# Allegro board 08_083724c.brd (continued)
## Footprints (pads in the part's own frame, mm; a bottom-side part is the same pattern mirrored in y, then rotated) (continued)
C1210H106
  rect 1.092x2.057 smd: 1(-1.646,0) 2(1.646,0)
C7343-31-2
  rect 3.353x2.438 smd: N(2.6,0) P(-2.6,0)
CNBERG1X6H205LD36
  rect 1.651x1.651 hole 1.143: 1(0,0)
  round 1.651 hole 1.143: 2(2.54,0) 3(5.08,0) 4(7.62,0) 5(10.16,0) 6(12.7,0)
CNKEY5016TP
  rect 4.699x3.429 smd: 1(0,0)
CNSAMTEC1X2H330LD36
  rect 1.651x1.651 hole 1.143: 1(-1.27,0)
  round 1.651 hole 1.143: 2(1.27,0)
CNTHMHDR2X5L500W200H215
  rect 1.143x1.143 hole 0.737: 1(0,0)
  round 1.143 hole 0.737: 2(0,1.27) 3(1.27,0) 4(1.27,1.27) 5(2.54,0) 6(2.54,1.27) 7(3.81,0) 8(3.81,1.27) 9(5.08,0) 10(5.08,1.27)
CNWURTH632723300011
  rect 0.305x1.194 smd: A1(-2.75,4.577) A2(-2.25,4.577) A3(-1.75,4.577) A4(-1.25,4.577) A5(-0.75,4.577) A6(-0.25,4.577) A7(0.25,4.577) A8(0.75,4.577) A9(1.25,4.577) A10(1.75,4.577) A11(2.25,4.577) A12(2.75,4.577)
  round 0.66 hole 0.406: B1(2.8,3.33) B2(2.4,2.63) B3(1.6,2.63) B4(1.2,3.33) B5(0.8,2.63) B6(0.4,3.33) B7(-0.4,3.33) B8(-0.8,2.63) B9(-1.2,3.33) B10(-1.6,2.63) B11(-2.4,2.63) B12(-2.8,3.33) GND1(-2,3.33) GND2(2,3.33)
  oval 0.991x1.6 hole 0.61x1.219: SH1(-4.27,2.18) SH2(4.27,2.18) SH3(4.27,-2.55) SH4(-4.27,-2.55)
  rect 0.203x0.991 smd: SH5(0,-0.005) SH6(0,-3.105)
CNWURTH693071010811
  rect 0.787x1.499 smd: 1(1.94,-3.099) 2(0.84,-2.699) 3(-0.26,-3.099) 4(-1.36,-3.299) 5(-2.46,-3.099) 6(-3.56,-3.299) 7(-4.66,-3.099) 8(-5.76,-3.099)
  rect 1.397x1.905 smd: 9_1(6.6,-6.952) 9_2(-6.55,-5.952)
  rect 1.803x1.397 smd: 10_1(0.752,7.201) 10_2(-4.948,7.201)
DFN2_1_6X1
  rect 0.508x0.787 smd: A(0.604,0) C(-0.604,0)
DFN8_3X2_PAD2_15X0_56_05-08-1702
  oval 0.305x0.838 smd: 1(-0.75,-0.95) 2(-0.25,-0.95) 3(0.25,-0.95) 4(0.75,-0.95) 5(0.75,0.95) 6(0.25,0.95) 7(-0.25,0.95) 8(-0.75,0.95)
  rect 2.159x0.61 smd: 9(0,0)
DO214ACH87
  rect 2.007x2.007 smd: A(2,0) C(-2,0)
FC2QFN15_F153A3FY_2
  rect 0.864x0.305 smd: 1(-1.618,0.95)
  rect 0.838x0.305 smd: 2(-1.631,0.45) 8(1.631,0.45) 9(1.631,0.95)
  rect 0.914x0.305 smd: 3(-1.593,-0.45) 7(1.593,-0.45)
  custom 0.241x0.241 smd: 4(-1.288,-1.438) 6(1.288,-1.438)
  custom 0.152x0.152 smd: 5(0,-0.473)
  custom 0.216x0.216 smd: 10(1.339,1.489) 15(-1.339,1.489)
  rect 0.305x0.838 smd: 11(0.75,1.756) 12(0.25,1.756) 13(-0.25,1.756) 14(-0.75,1.756)
FINGER274P_E4P
  rect 0.356x2.845 smd: 1(-32,0) 2(-31.75,0) 3(-31.5,0) 4(-31.25,0) 5(-31,0) 6(-30.75,0) 7(-30.5,0) 8(-30.25,0) 9(-30,0) 10(-29.75,0) 11(-29.5,0) 12(-29.25,0) 13(-29,0) 14(-28.75,0) 15(-28.5,0) 16(-28.25,0) 17(-28,0) 18(-27.75,0) 19(-27.5,0) 20(-27.25,0) 21(-27,0) 22(-26.75,0) 23(-26.5,0) 24(-26.25,0) 25(-26,0) 26(-25.75,0) 27(-25.5,0) 28(-25.25,0) 29(-25,0) 30(-24.75,0) 31(-24.5,0) 32(-24.25,0) 33(-24,0) 34(-23.75,0) 35(-23.5,0) 36(-23.25,0) 37(-23,0) 38(-22.75,0) 39(-22.5,0) 40(-22.25,0) 41(-22,0) 42(-21.75,0) 43(-21.5,0) 44(-21.25,0) 45(-21,0) 46(-20.75,0) 47(-20.5,0) 48(-20.25,0) 49(-20,0) 50(-19.75,0) 51(-19.5,0) 52(-19.25,0) 53(-19,0) 54(-18.75,0) 55(-18.5,0) 56(-18.25,0) 57(-18,0) 58(-17.75,0) 59(-17.5,0) 60(-17.25,0) 61(-17,0) 62(-16.75,0) 63(-16.5,0) 64(-16.25,0) 65(-16,0) 66(-15.75,0) 67(-15.5,0) 68(-15.25,0) 69(-15,0) 70(-14.75,0) 71(-14.5,0) 72(-14.25,0) 73(-14,0) 74(-13.75,0) 75(-13.5,0) 76(-13.25,0) 77(-13,0) 78(-12.75,0) 79(-12.5,0) 80(-12.25,0) 81(-12,0) 82(-11.75,0) 83(-11.5,0) 84(-11.25,0) 85(-11,0) 86(-10.75,0) 87(-10.5,0) 88(-10.25,0) 89(-10,0) 90(-9.75,0) 91(-9.5,0) 92(-9.25,0) 93(-9,0) 94(-8.75,0) 95(-8.5,0) 96(-8.25,0) 97(-8,0) 98(-7.75,0) 99(-7.5,0) 100(-7.25,0) 101(-7,0) 102(-6.75,0) 103(-6.5,0) 104(-6.25,0) 105(-6,0) 106(-5.75,0) 107(-5.5,0) 108(-5.25,0) 109(-5,0) 110(-4.75,0) 111(-4.5,0) 112(-4.25,0) 113(-4,0) 114(-3.75,0) 115(-3.5,0) 116(-3.25,0) 117(-3,0) 118(-2.75,0) 119(-2.5,0) 120(-2.25,0) 121(-2,0) 122(-1.75,0) 123(-1.5,0) 124(-1.25,0) 125(-1,0) 133(1,0) 134(1.25,0) 135(1.5,0) 136(1.75,0) 137(2,0) 138(2.25,0) 139(2.5,0) 140(2.75,0) 141(3,0) 142(3.25,0) 143(3.5,0) 144(3.75,0) 145(4,0) 146(4.25,0) 147(4.5,0) 148(4.75,0) 149(5,0) 150(5.25,0) 151(5.5,0) 152(5.75,0) 153(6,0) 154(6.25,0) 155(6.5,0) 156(6.75,0) 157(7,0) 158(7.25,0) 159(7.5,0) 160(7.75,0) 161(8,0) 162(8.25,0) 163(8.5,0) 164(8.75,0) 165(9,0) 166(9.25,0) 167(9.5,0) 168(9.75,0) 169(10,0) 170(10.25,0) 171(10.5,0) 172(10.75,0) 173(11,0) 174(11.25,0) 175(11.5,0) 176(11.75,0) 177(12,0) 178(12.25,0) 179(12.5,0) 180(12.75,0) 181(13,0) 182(13.25,0) 183(13.5,0) 184(13.75,0) 185(14,0) 186(14.25,0) 187(14.5,0) 188(14.75,0) 189(15,0) 190(15.25,0) 191(15.5,0) 192(15.75,0) 193(16,0) 194(16.25,0) 195(16.5,0) 196(16.75,0) 197(17,0) 198(17.25,0) 199(17.5,0) 200(17.75,0) 201(18,0) 202(18.25,0) 203(18.5,0) 204(18.75,0) 205(19,0) 206(19.25,0) 207(19.5,0) 208(19.75,0) 209(20,0) 210(20.25,0) 211(20.5,0) 212(20.75,0) 213(21,0) 214(21.25,0) 215(21.5,0) 216(21.75,0) 217(22,0) 218(22.25,0) 219(22.5,0) 220(22.75,0) 221(23,0) 222(23.25,0) 223(23.5,0) 224(23.75,0) 225(24,0) 226(24.25,0) 227(24.5,0) 228(24.75,0) 229(25,0) 230(25.25,0) 231(25.5,0) 232(25.75,0) 233(26,0) 234(26.25,0) 235(26.5,0) 236(26.75,0) 237(27,0) 238(27.25,0) 239(27.5,0) 240(27.75,0) 241(28,0) 242(28.25,0) 243(28.5,0) 244(28.75,0) 245(29,0) 246(29.25,0) 247(29.5,0) 248(29.75,0) 249(30,0) 250(30.25,0) 251(30.5,0) 252(30.75,0) 253(31,0) 254(31.25,0) 255(31.5,0) 256(31.75,0) 257(32,0) 258(32.25,0) 259(32.5,0) 260(32.75,0) 261(33,0) 262(33.25,0) 263(33.5,0) 264(33.75,0) 265(34,0) 266(34.25,0) 267(34.5,0) 268(34.75,0) 269(35,0) 270(35.25,0) 271(35.5,0) 272(35.75,0) 273(36,0) 274(36.25,0) 275(36.5,0) 276(36.75,0) 277(37,0) 278(37.25,0) 279(37.5,0) 280(37.75,0) 281(38,0)
  rect 4.826x2.845 smd: E1(-39.75,0) E2(-39.5,0) E3(-34.75,0) E4(-34.5,0)
L0805
  rect 1.194x1.448 smd: 1(-0.85,0) 2(0.85,0)
L1206
  rect 1.524x1.575 smd: 1(-1.714,0) 2(1.714,0)
LED0603
  rect 0.965x0.762 smd: A(0.8,0) C(-0.8,0)
LED0603-2
  rect 0.787x0.787 smd: A(0.787,0) C(-0.787,0)
LED0805_A
  rect 1.245x1.092 smd: A(1.172,0) C(-1.172,0)
LSML126W138H118
  rect 0.813x3.2 smd: 1(-0.902,0) 2(0.902,0)
LSMSQ157H122
  rect 0.965x3.708 smd: 1(-1.181,0) 2(1.181,0)
QFN16_2_6X1_8_A
  oval 0.203x0.787 smd: 1(-0.6,-0.9) 2(-0.2,-0.9) 3(0.2,-0.9) 4(0.6,-0.9) 9(0.6,0.9) 10(0.2,0.9) 11(-0.2,0.9) 12(-0.6,0.9)
  oval 0.787x0.203 smd: 5(1.3,-0.6) 6(1.3,-0.2) 7(1.3,0.2) 8(1.3,0.6) 13(-1.3,0.6) 14(-1.3,0.2) 15(-1.3,-0.2) 16(-1.3,-0.6)
QFN24_4X4_PAD2_1X2_1
  oval 0.305x0.991 smd: 1(-1.25,-2) 2(-0.75,-2) 3(-0.25,-2) 4(0.25,-2) 5(0.75,-2) 6(1.25,-2) 13(1.25,2) 14(0.75,2) 15(0.25,2) 16(-0.25,2) 17(-0.75,2) 18(-1.25,2)
  oval 0.991x0.305 smd: 7(2,-1.25) 8(2,-0.75) 9(2,-0.25) 10(2,0.25) 11(2,0.75) 12(2,1.25) 19(-2,1.25) 20(-2,0.75) 21(-2,0.25) 22(-2,-0.25) 23(-2,-0.75) 24(-2,-1.25)
  rect 2.108x2.108 smd: PAD(0,0)
QFN24_4X4_PAD2_5X2_5
  oval 0.305x0.991 smd: 1(-1.25,-2) 2(-0.75,-2) 3(-0.25,-2) 4(0.25,-2) 5(0.75,-2) 6(1.25,-2) 13(1.25,2) 14(0.75,2) 15(0.25,2) 16(-0.25,2) 17(-0.75,2) 18(-1.25,2)
  oval 0.991x0.305 smd: 7(2,-1.25) 8(2,-0.75) 9(2,-0.25) 10(2,0.25) 11(2,0.75) 12(2,1.25) 19(-2,1.25) 20(-2,0.75) 21(-2,0.25) 22(-2,-0.25) 23(-2,-0.75) 24(-2,-1.25)
  rect 2.489x2.489 smd: PAD(0,0)
QFN28_5X5_PAD3_5X3_5
  oval 0.305x0.838 smd: 1(-1.5,-2.45) 2(-1,-2.45) 3(-0.5,-2.45) 4(0,-2.45) 5(0.5,-2.45) 6(1,-2.45) 7(1.5,-2.45) 15(1.5,2.45) 16(1,2.45) 17(0.5,2.45) 18(0,2.45) 19(-0.5,2.45) 20(-1,2.45) 21(-1.5,2.45)
  oval 0.838x0.305 smd: 8(2.45,-1.5) 9(2.45,-1) 10(2.45,-0.5) 11(2.45,0) 12(2.45,0.5) 13(2.45,1) 14(2.45,1.5) 22(-2.45,1.5) 23(-2.45,1) 24(-2.45,0.5) 25(-2.45,0) 26(-2.45,-0.5) 27(-2.45,-1) 28(-2.45,-1.5)
  rect 3.505x3.505 smd: PAD(0,0)
QFN29_5X5_PAD1_66X1_7
  custom 0.087x0.087 smd: 1(-2.338,1.5) 2(-2.338,1) 3(-2.338,0.5) 4(-2.338,0) 5(-2.338,-0.5) 6(-2.338,-1) 7(-2.338,-1.5) 9(-1.437,-2.312) 10(-0.938,-2.312) 11(-0.437,-2.362) 12(0.437,-2.362) 13(0.938,-2.312) 14(1.437,-2.312) 16(2.338,-1.45) 17(2.338,-0.95) 18(2.338,-0.45) 19(2.338,0.45) 20(2.338,0.95) 21(2.338,1.45) 23(1.437,2.312) 24(0.938,2.312) 25(0.437,2.362) 26(-0.437,2.362) 27(-0.938,2.312) 28(-1.437,2.312)
  custom 0.249x0.249 smd: 8(-2.029,-2.075) 15(2.029,-2.075) 22(2.029,2.075) 29(-2.029,2.075)
  rect 1.75x1.71 smd: 30(0,0)
R0201
  rect 0.305x0.406 smd: 1(-0.318,0) 2(0.318,0)
R0402
  rect 0.635x0.737 smd: 1(-0.5,0) 2(0.5,0)
R0603
  rect 0.787x0.991 smd: 1(-0.85,0) 2(0.85,0)
R0805
  rect 1.041x1.397 smd: 1(-0.95,0) 2(0.95,0)
R1206-4P
  rect 1.753x1.092 smd: 1(-1.376,-0.696) 2(1.376,-0.696) 3(1.376,0.696) 4(-1.376,0.696)
R2512H35
  rect 2.108x3.988 smd: 1(-3.104,0) 2(3.104,0)
SC70-5_A
  rect 0.406x0.94 smd: 1(-0.65,-1.1) 2(0,-1.1) 3(0.65,-1.1) 4(0.65,1.1) 5(-0.65,1.1)
SO8
  rect 0.61x2.184 smd: 1(-1.905,-2.54) 2(-0.635,-2.54) 3(0.635,-2.54) 4(1.905,-2.54) 5(1.905,2.54) 6(0.635,2.54) 7(-0.635,2.54) 8(-1.905,2.54)
SOT23-5L
  rect 0.508x1.524 smd: 1(-0.95,-1.17) 2(0,-1.17) 3(0.95,-1.17) 4(0.95,1.17) 5(-0.95,1.17)
SOT23-5L-2
  rect 0.61x1.194 smd: 1(-0.95,-1.15) 2(0,-1.15) 3(0.95,-1.15) 4(0.95,1.15) 5(-0.95,1.15)
SOT23_6-3
  rect 0.635x1.067 smd: 1(-0.95,-1.1) 2(0,-1.1) 3(0.95,-1.1) 4(0.95,1.1) 5(0,1.1) 6(-0.95,1.1)
SOT353
  rect 0.33x0.94 smd: 1(-0.65,-0.89) 2(0,-0.89) 3(0.65,-0.89) 4(0.65,0.89) 5(-0.65,0.89)
SWSML137W244H177
  rect 1.092x1.499 smd: 1A(0,-4.449) 1B(0,4.449)
SWSML248W244H185
  rect 1.397x2.108 smd: 1(-1.998,-4.454) 2(-1.998,4.454) 3(1.998,-4.454) 4(1.998,4.454)
SWSMSQ394H268
  rect 1.194x2.591 smd: 1(-2.54,-5.995) 2(2.54,5.995) 4(2.54,-5.995) 8(-2.54,5.995) C1(0,-5.995) C2(0,5.995)
TBGA24
  round 0.33 smd: A2(-2,-1) A3(-2,0) A4(-2,1) A5(-2,2) B1(-1,-2) B2(-1,-1) B3(-1,0) B4(-1,1) B5(-1,2) C1(0,-2) C2(0,-1) C3(0,0) C4(0,1) C5(0,2) D1(1,-2) D2(1,-1) D3(1,0) D4(1,1) D5(1,2) E1(2,-2) E2(2,-1) E3(2,0) E4(2,1) E5(2,2)
TPSMC30
  round 0.762 smd: 1(0,0)
TSSOP14
  rect 1.651x0.33 smd: 1(-2.87,1.956) 2(-2.87,1.306) 3(-2.87,0.655) 4(-2.87,0.005) 5(-2.87,-0.645) 6(-2.87,-1.295) 7(-2.87,-1.946) 8(2.87,-1.946) 9(2.87,-1.295) 10(2.87,-0.645) 11(2.87,0.005) 12(2.87,0.655) 13(2.87,1.306) 14(2.87,1.956)
unnamed#2
  round 5.994 hole 3.2 unplated: (0,0)
VQFN12_2X2_5
  oval 1.041x0.406 smd: 1(-0.675,0.35) 2(-0.675,-0.35) 7(0.675,-0.35) 8(0.675,0.35)
  oval 0.203x0.61 smd: 3(-0.75,-1.15) 4(-0.25,-1.15) 5(0.25,-1.15) 6(0.75,-1.15) 9(0.75,1.15) 10(0.25,1.15) 11(-0.25,1.15) 12(-0.75,1.15)
WLCSP20-2
  round 0.203 smd: A1(-0.8,-0.6) A2(-0.8,-0.2) A3(-0.8,0.2) A4(-0.8,0.6) B1(-0.4,-0.6) B2(-0.4,-0.2) B3(-0.4,0.2) B4(-0.4,0.6) C1(0,-0.6) C2(0,-0.2) C3(0,0.2) C4(0,0.6) D1(0.4,-0.6) D2(0.4,-0.2) D3(0.4,0.2) D4(0.4,0.6) E1(0.8,-0.6) E2(0.8,-0.2) E3(0.8,0.2) E4(0.8,0.6)
XSM4PL126W98H39
  rect 1.194x0.991 smd: 1(-1.27,-0.989) 2(1.27,-0.989) 3(1.27,0.989) 4(-1.27,0.989)
YSML79W63H32
  rect 0.762x0.66 smd: 1(-0.66,-0.508) 2(0.66,-0.508) 3(0.66,0.508) 4(-0.66,0.508)
YSML126W98H31
  rect 1.397x1.194 smd: 1(-1.1,-0.95) 2(1.1,-0.95) 3(1.1,0.95) 4(-1.1,0.95)

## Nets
1V8_LDO0: C140.1 TP30.1(N1) U16.29
1V8_LDO2: C123.1 C124.1 TP29.1(N1) U16.6
1V8_LDO3: C138.1 C234.1 TP31.1(N1) U16.8
3V3: C61.2(N2) C63.1 C65.2(N2) C67.2(N2) C119.2(N2) C121.2(N2) C139.1 C141.1 C142.1 C143.1 C248.1 C249.1 C251.1 C252.1 L1.2(N2) P6.4 R104.1 R104.3 R116.1 R120.1 R124.2(N2) R221.1 U2.11 U9.A3(VSD) U10.E6 U10.F5 U10.J10 U10.K9 U16.11 U16.12 U16.18 U16.19 U22.3 U22.4
DGND: C1.1 C2.1 C3.1 C4.1 C5.2(N2) C6.1 C7.1 C8.1 C9.1 C10.1 C11.1 C12.1 C13.1 C14.2(N2) C15.1 C16.1 C17.1 C18.1 C19.1 C20.1 C21.1 C22.1 C23.1 C24.2(N2) C25.2(N2) C26.2(N2) C27.2(N2) C28.2(N2) C29.2(N2) C30.2(N2) C31.2(N2) C32.1 C33.1 C34.2(N2) C35.2(N2) C36.2(N2) C37.1 C38.2(N2) C39.2(N2) C40.2(N2) C41.2(N2) C42.2(N2) C43.2(N2) C44.2(N2) C45.2(N2) C46.2(N2) C47.2(N2) C48.2(N2) C49.2(N2) C50.1 C51.1 C52.1 C53.2(N2) C54.1 C55.2(N2) C56.1 C57.1 C58.1 C59.2(N2) C60.2(N2) C61.1 C62.1 C63.2(N2) C64.1 C65.1 C66.2(N2) C67.1 C68.1 C69.1 C70.1 C71.1 C72.2(N2) C86.2(N2) C87.2(N2) C88.2(N2) C89.2(N2) C90.2(N2) C91.2(N2) C92.2(N2) C93.2(N2) C94.2(N2) C95.2(N2) C96.2(N2) C97.2(N2) C98.1 C99.2(N2) C100.1 C101.1 C102.1 C103.1 C104.1 C105.2(N2) C106.2(N2) C107.2(N2) C108.1 C109.2(N2) C110.2(N2) C111.2(N2) C112.1 C113.2(N2) C114.1 C115.2(N2) C116.2(N2) C117.1 C118.1 C119.1 C120.2(N2) C121.1 C122.2(N2) C123.2(N2) C124.2(N2) C125.2(N2) C126.2(N2) C127.2(N2) C128.2(N2) C129.2(N2) C130.2(N2) C131.2(N2) C132.2(N2) C133.2(N2) C134.2(N2) C135.2(N2) C136.2(N2) C137.2(N2) C138.2(N2) C139.2(N2) C140.2(N2) C141.2(N2) C142.2(N2) C143.2(N2) C144.2(N2) C145.1 C146.2(N2) C147.1 C148.1 C149.1 C150.1 C151.1 C152.1 C153.1 C154.1 C155.1 C156.1 C157.1 C158.1 C159.1 C160.1 C161.1 C162.1 C163.2(N2) C164.2(N2) C165.2(N2) C166.2(N2) C167.2(N2) C168.2(N2) C169.2(N2) C170.2(N2) C171.2(N2) C172.2(N2) C173.2(N2) C174.2(N2) C175.2(N2) C176.2(N2) C177.2(N2) C178.2(N2) C179.2(N2) C180.2(N2) C181.2(N2) C182.2(N2) C183.2(N2) C184.2(N2) C185.2(N2) C186.2(N2) C187.2(N2) C188.2(N2) C189.2(N2) C190.2(N2) C191.2(N2) C192.2(N2) C193.2(N2) C194.2(N2) C195.2(N2) C196.2(N2) C197.2(N2) C198.2(N2) C199.2(N2) C200.2(N2) C201.2(N2) C202.2(N2) C203.2(N2) C204.2(N2) C205.2(N2) C206.2(N2) C207.2(N2) C208.2(N2) C209.2(N2) C210.2(N2) C211.2(N2) C212.2(N2) C213.2(N2) C214.2(N2) C215.2(N2) C216.2(N2) C217.2(N2) C218.2(N2) C219.2(N2) C220.2(N2) C221.2(N2) C222.2(N2) C223.2(N2) C224.2(N2) C225.2(N2) C226.2(N2) C227.2(N2) C228.2(N2) C229.2(N2) C230.2(N2) C231.2(N2) C232.2(N2) C233.2(N2) C234.2(N2) C235.2(N2) C236.2(N2) C238.2(N2) C239.2(N2) C240.2(N2) C241.1 C242.2(N2) C243.2(N2) C244.2(N2) C245.2(N2) C246.N(N2) C247.2(N2) C248.2(N2) C249.2(N2) C250.2(N2) C251.2(N2) C252.2(N2) C253.2(N2) C254.2(N2) C255.2(N2) C256.2(N2) C257.2(N2) C258.2(N2) C262.2(N2) D1.2 D1.5 D2.2 D3.A(P) D6.2 D8.A(P) P2.A1 P2.A12 P2.B1 P2.B12 P2.GND1 P2.GND2 P3.A1 P3.A12 P3.B1 P3.B12 P3.GND1 P3.GND2 P4.3 P4.5 P5.3 P5.5 P6.6 P6.9_1(N9) P6.9_2 P8.27 P8.28 P8.49 P8.50 P8.71 P8.72 P8.73 P8.85 P8.90 P8.97 P8.109 P8.110 P8.121 P8.124 P8.133 P8.134 P8.145 P8.148 P8.154 P8.157 P8.160 P8.166 P8.169 P8.174 P8.180 P8.181 P8.186 P8.191 P8.193 P8.196 P8.203 P8.206 P8.213 P8.216 P8.223 P8.229 P8.235 P8.238 P8.251 P8.260 P8.265 P8.268 P8.272 P8.278 P8.279 P8.280 P8.281 P8.E3 P8.E4 P12.5 P12.6(N6) R1.2(N2) R2.2(N2) R3.2(N2) R6.2(N2) R11.2(N2) R12.2(N2) R13.2(N2) R15.2(N2) R19.2(N2) R21.2(N2) R40.2(N2) R42.2(N2) R45.2(N2) R50.2(N2) R51.2(N2) R67.2(N2) R68.2(N2) R82.2(N2) R84.2(N2) R86.2(N2) R91.2(N2) R93.2(N2) R94.2(N2) R103.2(N2) R119.2(N2) R130.2(N2) R147.2(N2) R153.2(N2) R156.2(N2) R166.1 R167.1 R168.1 R169.1 R170.1 R206.2(N2) R208.2(N2) R209.2(N2) R211.2(N2) R212.2(N2) S4.1 S4.2 TP28.1(N1) U1.A1 U1.A11 U1.A22 U1.AA2 U1.AA5 U1.AA14 U1.AA15 U1.AA16 U1.AA17 U1.AA21(GND_99) U1.AB1 U1.AB4 U1.AB5 U1.AB14 U1.AB15 U1.AB16 U1.AB17 U1.AB22 U1.B2 U1.B6 U1.B17 U1.B21 U1.C1 U1.C3 U1.C5 U1.C7 U1.C16 U1.C18 U1.C20 U1.D4 U1.D6 U1.D8 U1.D12 U1.D15 U1.D17 U1.D19 U1.D22 U1.E5 U1.E18 U1.F6 U1.F11 U1.F13 U1.F17 U1.G16 U1.H8 U1.H9 U1.H10 U1.H11 U1.H12 U1.H13 U1.H14 U1.H15 U1.H17 U1.J1 U1.J7 U1.J10 U1.J13 U1.J16 U1.L1 U1.L7 U1.L9 U1.L10 U1.L11 U1.L12 U1.L13 U1.L14 U1.L16 U1.N1 U1.N7 U1.N9 U1.N10 U1.N11 U1.N12 U1.N13 U1.N14 U1.N16 U1.N22 U1.P22 U1.R7 U1.R16 U1.T7 U1.T9 U1.T11 U1.T13 U1.T15 U1.T16 U1.U6 U1.U17 U1.V5 U1.V8 U1.V15 U1.V16 U1.V17 U1.V18 U1.W4 U1.W6 U1.W14 U1.W15 U1.W16 U1.W17 U1.W18 U1.W19 U1.Y3 U1.Y5 U1.Y6 U1.Y14 U1.Y15 U1.Y16 U1.Y17 U1.Y20 U2.4 U2.6 U2.8 U3.A3 U3.A10 U3.AB3 U3.AB5 U3.AB8 U3.AB10 U3.C1 U3.C5 U3.C8 U3.C12 U3.D2 U3.D4 U3.D9 U3.D11 U3.E1 U3.E5 U3.E8 U3.E12 U3.G1 U3.G3 U3.G5 U3.G8 U3.G10 U3.G12 U3.J1 U3.J3 U3.J10 U3.J12 U3.K2 U3.K4 U3.K9 U3.K11 U3.N2 U3.N4 U3.N9 U3.N11 U3.P1 U3.P3 U3.P10 U3.P12 U3.T1 U3.T3 U3.T5 U3.T8 U3.T10 U3.T12 U3.V1 U3.V5 U3.V8 U3.V12 U3.W2 U3.W4 U3.W9 U3.W11 U3.Y1 U3.Y5 U3.Y8 U3.Y12 U4.19 U4.PAD U5.B3 U5.C1 U5.E5(VSSQ_2) U6.B3 U7.6 U7.7 U7.8 U7.9 U7.10 U7.11 U7.12 U8.6 U9.C2 U9.C3 U10.A6 U10.C4 U10.E7 U10.G5 U10.H10 U10.J5 U10.K8 U10.N2 U10.N5 U10.P4 U10.P6 U13.7 U14.3 U14.PAD U15.2 U15.5(WP) U16.4 U16.26 U16.30 U17.2 U17.5(WP) U18.3 U19.3 U20.9(ST) U20.12 U21.1 U21.9 U22.PAD U23.3 U29.7 Y1.2 Y1.4 Y2.2 Y4.2
VDD_EXT: C1.2(N2) C2.2(N2) C3.2(N2) C4.2(N2) C5.1 C6.2(N2) C7.2(N2) C8.2(N2) C9.2(N2) C32.2(N2) C53.1 C54.2(N2) C55.1 C56.2(N2) C57.2(N2) C58.2(N2) C59.1 C60.1 C62.2(N2) C68.2(N2) C69.2(N2) C70.2(N2) C71.2(N2) C72.1 C87.1 C90.1 C96.1 C125.1 C131.1 C132.1 C133.1 C134.1 C137.1 C163.1 C164.1 C165.1 C166.1 C167.1 C168.1 C169.1 C170.1 C171.1 C226.1 C228.1 C230.1 C232.1 C236.1 C241.2(N2) C242.1 C253.1 C254.1 C255.1 C256.1 C262.1 DS1.A(P) DS2.A(P) DS3.A(P) DS4.A(P) DS5.A(P) DS6.A(P) DS9.A(P) DS11.A(P) E2.2(N2) E3.2(N2) E4.2(N2) JP2.1 P10.2(N2) R4.1 R8.1 R9.1 R10.1 R14.1 R17.1 R18.1 R20.1 R38.1 R39.1 R44.1 R46.1 R47.1 R48.1 R66.1 R81.1 R83.1 R95.1 R96.1 R101.1 R109.2(N2) R112.2(N2) R113.1 R115.1 R117.1 R123.1 R127.1 R129.1 R132.1 R133.1 R134.1 R135.1 R136.1 R137.1 R138.1 R139.1 R140.1 R141.1 R145.1 R154.1 R155.1 R159.1 R207.2(N2) S2.C1 S2.C2 TP23.1(N1) U1.G7 U1.H7 U1.H16 U1.K7 U1.K16 U1.M7 U1.M16 U1.P7 U1.P16 U1.T10 U1.T12 U1.T14 U1.T22 U3.F1 U3.F12 U3.G4 U3.G9 U3.T4 U3.T9 U3.U1 U3.U12 U4.21(VCC) U5.B4 U5.D1 U5.E4 U6.B4 U7.14(VDD) U8.14(VDD) U9.A2 U10.C6 U10.M4 U10.N4 U10.P3 U10.P5 U13.1 U13.8 U15.4 U17.4 U18.5 U19.5 U21.4(VM) U21.5 U22.17(VDDIO) U22.21 U29.14(VCC) Y2.4(VDD) Y4.1 Y4.4(VDD)
VDD_INPUT: C97.1 C107.1 C128.1 C129.1 C135.1 C136.1 C239.1 C240.1 C243.1 C247.1 D7.C TP22.1(N1) U2.1 U2.3 U2.7 U20.1 U20.8 U23.7
VDD_INT: C34.1 C144.1 C172.1 C173.1 C174.1 C175.1 C176.1 C177.1 C178.1 C179.1 C180.1 C181.1 C182.1 C183.1 C184.1 C185.1 C186.1 C187.1 C188.1 C189.1 C190.1 C191.1 C192.1 C193.1 C194.1 C195.1 C196.1 C197.1 C198.1 C199.1 C200.1 C201.1 C202.1 C203.1 C204.1 C205.1 C206.1 C207.1 C208.1 C209.1 C210.1 C211.1 C212.1 C213.1 C214.1 C215.1 C216.1 C217.1 C218.1 C219.1 C220.1 C221.1 C222.1 C223.1 C224.1 P7.2(N2) R125.2(N2) R126.2(N2) R131.2(N2) TP20.1(N1) U1.J8 U1.J9 U1.J11 U1.J12 U1.J14 U1.J15 U1.K8 U1.K9 U1.K12 U1.K13 U1.K14 U1.K15 U1.L8 U1.L15 U1.M8 U1.M9 U1.M12 U1.M13 U1.M14 U1.M15 U1.N8 U1.N15 U1.P8 U1.P9 U1.P10 U1.P11 U1.P12 U1.P13 U1.P14 U1.P15 U1.R8 U1.R9 U1.R10 U1.R11 U1.R12 U1.R13 U1.R14 U1.R15 U1.T8
VDD_LPDD4_IO: C10.2(N2) C11.2(N2) C12.2(N2) C13.2(N2) C14.1 C15.2(N2) C16.2(N2) C17.2(N2) C18.2(N2) C19.2(N2) C20.2(N2) C21.2(N2) C22.2(N2) C23.2(N2) C35.1 C36.1 C38.1 C39.1 C40.1 C41.1 C42.1 C43.1 C44.1 C45.1 C46.1 C47.1 C48.1 C49.1 C50.2(N2) C51.2(N2) C52.2(N2) C98.2(N2) C99.1 C100.2(N2) C101.2(N2) C102.2(N2) C103.2(N2) C104.2(N2) C105.1 C106.1 C108.2(N2) C109.1 C110.1 C111.1 C112.2(N2) C113.1 C114.2(N2) C115.1 C116.1 C117.2(N2) C118.2(N2) C120.1 C122.1 C130.1 C145.2(N2) C146.1 C147.2(N2) C148.2(N2) C149.2(N2) C150.2(N2) C151.2(N2) C152.2(N2) C153.2(N2) C154.2(N2) C155.2(N2) C156.2(N2) C157.2(N2) C158.2(N2) C159.2(N2) C160.2(N2) C161.2(N2) C162.2(N2) C225.1 C227.1 C229.1 C231.1 C233.1 P9.2(N2) R16.1 R106.2(N2) R128.2(N2) R148.2(N2) R149.2(N2) R150.1 TP21.1(N1) U1.D9 U1.D10 U1.D11 U1.D13 U1.D14 U1.E8 U1.E9 U1.E10 U1.E11 U1.E12 U1.E13 U1.E14 U1.E15 U1.F8 U1.F9 U1.F10 U1.F14 U1.F15 U1.G8 U1.G9 U1.G10 U1.G11 U1.G12 U1.G13 U1.G14 U1.G15 U3.A4 U3.A9 U3.AA3 U3.AA5 U3.AA8 U3.AA10 U3.AB4 U3.AB9 U3.B3 U3.B5 U3.B8 U3.B10 U3.D1 U3.D5 U3.D8 U3.D12 U3.F3 U3.F5 U3.F8 U3.F10 U3.H1 U3.H5 U3.H8 U3.H12 U3.K1 U3.K3 U3.K10 U3.K12 U3.N1 U3.N3 U3.N10 U3.N12 U3.R1 U3.R5 U3.R8 U3.R12 U3.U3 U3.U5 U3.U8 U3.U10 U3.W1 U3.W5 U3.W8 U3.W12
VDD_SOM: P8.E1 P8.E2 R164.1
_N14: C26.1 C27.1 E3.1 U1.K10 U1.K11 U1.M10 U1.M11
_N15: C25.1 R143.2(N2) R158.1 Y1.1
_N16: C24.1 R142.1 R158.2(N2) Y1.3(IN/OUT2)
_N31: C28.1 C29.1 E4.1 U1.R22
_N36: C30.1 C31.1 C245.1 E2.1 U1.F12
_N50: JP2.2(S2) P5.1
_N51: JP1.2(S2) P5.10
_N72: R153.1 U1.K21
_N74: TP24.1(N1) U1.M20
_N82: R43.2(N2) R45.1 U6.B2
_N89: R52.2(N2) U10.M6
_N100: C64.2(N2) U10.C2
_N101: R50.1 U7.13
_N102: R52.1 U7.1
_N105: R51.1 U8.13
_N108: U8.1 U10.A3
_N109: R57.2(N2) R60.2(N2) U19.4(Y)
_N110: U8.4 U10.A4
_N111: U8.8 U10.A5
_N112: U8.11 U10.B2
_N113: U8.12 U9.B1
_N114: U8.9 U9.A1
_N115: U8.3 U9.E1
_N116: U8.16 U9.D1
_N117: U7.3 U9.C1
_N118: U7.16 U9.D2
_N119: R53.1 U9.D3
_N121: P6.5 R53.2(N2)
_N123: R54.1 U9.C4
_N124: R55.1 U9.D4
_N125: R58.1 U9.E4
_N126: R56.1 U9.A4
_N127: R59.1 U9.B4
_N128: R57.1 U9.B2
_N130: P6.7 R55.2(N2)
_N131: P6.8 R58.2(N2)
_N132: P6.10_1 P6.10_2 R66.2(N2) U19.2
_N133: P6.2 R59.2(N2)
_N140: P6.3 R54.2(N2)
_N144: P6.1 R56.2(N2)
_N147: R46.2(N2) R49.1 U6.D2
_N177: R11.1 TP27.1(N1) U1.K22
_N243: R113.2(N2) S4.3 S4.4(N4) U18.1
_N244: DS11.C R160.1
_N245: R129.2(N2) U21.3
_N246: R130.1 U21.6
_N247: R127.2(N2) U18.4(Y) U21.2
_N248: C127.1 U21.7
_N254: R105.1 R167.2(N2) U20.5
_N255: R107.1 R168.2(N2) U20.6
_N256: R111.2(N2) R169.2(N2) U20.3
_N257: R165.1 R166.2(N2) U20.4
_N258: R170.2(N2) U20.10
_N259: C250.1 U20.11
_N260: R111.1 R163.2(N2) R165.2(N2) U20.2
_N261: R105.2(N2) R107.2(N2) R164.2(N2) U20.7
_N282: P4.1 R4.2(S2)
_N283: P4.10 R5.2(S2)
_N287: DS9.C R102.1
_N296: DS1.C R7.1
_N299: L3.2(N2) P9.1 R128.1
_N307: L2.1 U16.10
_N308: R125.1 U16.9
_N321: U13.10 U14.26
_N322: U13.11 U14.25
_N323: R89.2(N2) U13.12 U14.24
_N324: R88.2(N2) U13.13 U14.23
_N325: R85.2(N2) R86.1 U14.8
_N326: R87.2(N2) U14.9
_N327: R90.2(N2) U14.18
_N328: R92.2(N2) U14.19
_N329: DS7.C R90.1
_N330: DS8.C R92.1
_N331: C88.1 C89.1 E1.2(N2) R85.1 U14.7(VREGIN)
_N350: R26.2(N2) U4.18
_N351: R36.2(N2) U4.17
_N352: R37.2(N2) U4.16
_N353: DS6.C R42.1
_N354: DS4.C R37.1
_N355: DS3.C R36.1
_N356: DS2.C R26.1
_N358: L4.1 U16.17
_N360: L3.1 U16.20
_N361: R106.1 U16.21
_N362: R109.1 U16.16
_N367: D2.1 P2.B5 R94.1
_N368: D2.3 P2.A5 R93.1
_N369: C95.1 P2.SH1 P2.SH2 P2.SH3 P2.SH4 P2.SH5 P2.SH6 R91.1
_N375: C126.1 U16.7
_N376: C235.1 R104.2 R104.4(V_2) U16.28
_N409: R101.2(N2) Y2.1
_N410: R114.1 Y2.3
_N541: R144.1 U1.J20
_N544: R177.1 U1.J21
_N552: R24.2(N2) U5.A3
_N553: R22.2(N2) U5.C2
_N554: R27.1 U5.C3
_N555: R29.1 U5.D4
_N556: R32.1 U5.D2
_N557: R28.1 U5.D3
_N558: R23.2(N2) U5.B2
_N559: R35.1 U5.E1
_N560: R30.1 U5.D5
_N561: R34.1 U5.E3
_N562: R33.1 U5.C4
_N563: R31.1 U5.E2
_N575: R68.1 U1.B19
_N576: R16.2(N2) U3.A5(ZQ0)
_N918: DS10.C R12.1
_N947: L5.1 U16.13
_N948: L2.2(N2) L5.2(N2) P7.1 R126.1
_N949: R131.1 U16.14
_N970: C237.1 U2.2
_N971: C237.2(N2) L1.1 U2.5
_N973: C238.1 U2.9 U2.10
_N1006: JP7.1 JP8.2(S2) P4.6
_N1008: R116.2(N2) U2.13
_N1009: R119.1 R120.2(N2) U2.14
_N1076: U13.3 U29.6
_N1077: TP16.1(N1) U13.4 U29.8
_N1078: TP17.1(N1) U13.5 U29.11
_N1079: U13.2 U29.3
_N1103: L4.2(N2) P10.1 R112.1
_N1111: R25.2(N2) U5.B1
_N1180: DS5.C R41.1
BMODE0: P8.243 P12.1 R1.1 S2.1 U1.F19
BMODE1: P8.245 P12.2 R2.1 S2.2 U1.H18
BMODE2: P8.247 P12.3 R3.1 S2.4 U1.D21
BMODE3: P8.249 P12.4 R6.1 S2.8 U1.F20
BP_ALERT_N: C33.2(N2) TP33.1(N1) U1.G18
BP_VREF: C37.2(N2) TP32.1(N1) U1.D2
CA0_A: R191.1 U1.C14
CA0_A_X: R191.2(N2) U3.H2
CA0_B: R182.1 U1.B10
CA0_B_X: R182.2(N2) U3.R2
CA1_A: R190.1 U1.B12
CA1_A_X: R190.2(N2) U3.J2
CA1_B: R183.1 U1.C10
CA1_B_X: R183.2(N2) U3.P2
CA2_A: R189.1 U1.C12
CA2_A_X: R189.2(N2) U3.H9
CA2_B: R184.1 U1.C11
CA2_B_X: R184.2(N2) U3.R9
CA3_A: R188.1 U1.B14
CA3_A_X: R188.2(N2) U3.H10
CA3_B: R185.1 U1.C9
CA3_B_X: R185.2(N2) U3.R10
CA4_A: R187.1 U1.C13
CA4_A_X: R187.2(N2) U3.H11
CA4_B: R186.1 U1.B11
CA4_B_X: R186.2(N2) U3.R11
CA5_A: R179.1 U1.B13
CA5_A_X: R179.2(N2) U3.J11
CA5_B: R180.1 U1.B9
CA5_B_X: R180.2(N2) U3.P11
CARRIER_DETECT*: P8.262 R102.2(N2)
CK_C_A: U1.A15 U3.J9
CK_C_B: U1.A6 U3.P9
CK_T_A: U1.A16 U3.J8
CK_T_B: U1.A7 U3.P8
CKE0_A: R118.1 U1.E16
CKE0_A_X: R118.2(N2) U3.J4
CKE0_B: R98.1 U1.E7
CKE0_B_X: R98.2(N2) U3.P4
CKE1_A: R122.2(N2) U1.C15
CKE1_A_X: R122.1 U3.J5
CKE1_B: R121.2(N2) U1.C8
CKE1_B_X: R121.1 U3.P5
CS0_A: R192.1 U1.A17
CS0_A_X: R192.2(N2) U3.H4
CS0_B: R181.1 U1.A5
CS0_B_X: R181.2(N2) U3.R4
CS1_A: U1.A14 U3.H3
CS1_B: U1.A8 U3.R3
DAI0_PIN01: P8.29 U1.N17
DAI0_PIN02: P8.31 U1.N18
DAI0_PIN03: P8.33 U1.P20
DAI0_PIN04: P8.35 U1.N20
DAI0_PIN05: P8.37 U1.N19
DAI0_PIN06: P8.39 U1.P17
DAI0_PIN07: P8.41 U1.R18
DAI0_PIN08: P8.43 U1.T18
DAI0_PIN09: P8.45 U1.P18
DAI0_PIN10: P8.47 U1.R20
DAI0_PIN11: P8.30 U1.P19
DAI0_PIN12: P8.32 U1.R17
DAI0_PIN13: P8.34 U1.R19
DAI0_PIN14: P8.36 U1.T19
DAI0_PIN15: P8.38 U1.T20
DAI0_PIN16: P8.40 U1.U20
DAI0_PIN17: P8.42 U1.U21
DAI0_PIN18: P8.44 U1.V22
DAI0_PIN19: P8.46 U1.U18
DAI0_PIN20: P8.48 U1.V20
DAI1_PIN01: P8.51 U1.U22
DAI1_PIN02: P8.53 U1.V21
DAI1_PIN03: P8.55 U1.T17
DAI1_PIN04: P8.57 U1.Y22
DAI1_PIN05: P8.59 U1.W22
DAI1_PIN06: P8.61 U1.AA22
DAI1_PIN07: P8.63 U1.W21
DAI1_PIN08: P8.65 U1.Y21
DAI1_PIN09: P8.67 U1.Y18
DAI1_PIN10: P8.69 U1.AB21
DAI1_PIN11: P8.52 U1.AB20
DAI1_PIN12: P8.54 U1.W20
DAI1_PIN13: P8.56 U1.V19
DAI1_PIN14: P8.58 U1.AA20
DAI1_PIN15: P8.60 U1.Y19
DAI1_PIN16: P8.62 U1.U19
DAI1_PIN17: P8.64 U1.AB19
DAI1_PIN18: P8.66 U1.AB18
DAI1_PIN19: P8.68 U1.AA19
DAI1_PIN20: P8.70 U1.AA18
DMI0_A: U1.A20 U3.C3
DMI0_B: U1.B8 U3.Y3
DMI1_A: U1.B15 U3.C10
DMI1_B: U1.A2 U3.Y10
DQ0_A: U1.C17 U3.B2
DQ0_B: U1.D7 U3.AA2
DQ1_A: U1.E19 U3.C2
DQ1_B: U1.C4 U3.Y2
DQ2_A: U1.D16 U3.E2
DQ2_B: U1.C6 U3.V2
DQ3_A: U1.D18 U3.F2
DQ3_B: U1.C2 U3.U2
DQ4_A: U1.E17 U3.F4
DQ4_B: U1.B1 U3.U4
DQ5_A: U1.F18 U3.E4
DQ5_B: U1.B5 U3.V4
DQ6_A: U1.F16 U3.C4
DQ6_B: U1.B7 U3.Y4
DQ7_A: U1.G17 U3.B4
DQ7_B: U1.B3 U3.AA4
DQ8_A: U1.B22 U3.B11
DQ8_B: U1.F5 U3.AA11
DQ9_A: U1.B20 U3.C11
DQ9_B: U1.D1 U3.Y11
DQ10_A: U1.B18 U3.E11
DQ10_B: U1.G6 U3.V11
DQ11_A: U1.C21 U3.F11
DQ11_B: U1.E4 U3.U11
DQ12_A: U1.D20 U3.F9
DQ12_B: U1.D5 U3.U9
DQ13_A: U1.A21 U3.E9
DQ13_B: U1.F7 U3.V9
DQ14_A: U1.B16 U3.C9
DQ14_B: U1.D3 U3.Y9
DQ15_A: U1.C19 U3.B9
DQ15_B: U1.E6 U3.AA9
DQS0_C_A: U1.A18 U3.E3
DQS0_C_B: U1.A9 U3.V3
DQS0_T_A: U1.A19 U3.D3
DQS0_T_B: U1.A10 U3.W3
DQS1_C_A: U1.A13 U3.E10
DQS1_C_B: U1.A3 U3.V10
DQS1_T_A: U1.A12 U3.D10
DQS1_T_B: U1.A4 U3.W10
EEPROM_ID0: P8.264 R95.2(N2) U15.1
EEPROM_ID1: P8.266 R96.2(N2) U15.3
EMSI0_CLK: R176.2(N2) TP42.1(N1) U7.2
EMSI0_CLK_X: R176.1 U1.U8
EMSI0_CMD: TP41.1(N1) U1.U7 U7.5
EMSI0_CMD_EMMC: U7.4 U10.M5
EMSI0_D0: TP19.1(N1) U1.U10 U8.2
EMSI0_D1: TP34.1(N1) U1.U9 U8.5
EMSI0_D2: TP35.1(N1) U1.V11 U8.7
EMSI0_D3: TP36.1(N1) U1.U11 U8.10
EMSI0_D4: TP37.1(N1) U1.V12 U10.B3
EMSI0_D5: TP38.1(N1) U1.U13 U10.B4
EMSI0_D6: TP39.1(N1) U1.U16 U10.B5
EMSI0_D7: TP40.1(N1) U1.U12 U10.B6
EMSI0_DS: TP43.1(N1) U1.U14 U10.H5
EMSI0_RST*: R154.2(N2) R157.2(N2) TP44.1(N1) U1.U15 U10.K5
HADC_VIN0: P8.74 U1.L22
HADC_VIN1: P8.76 U1.T21
HADC_VIN2: P8.78 U1.L21
HADC_VIN3: P8.80 U1.M21
HADC_VIN4: P8.82 U1.R21
HADC_VIN5: P8.84 U1.P21
HADC_VIN6: P8.86 U1.N21
HADC_VIN7: P8.88 U1.M22
JTG1_TCK: JP5.2(S2) P5.4 U1.J6
JTG1_TDI: JP7.2(S2) P5.8 U1.H5
JTG1_TDO: JP3.2(S2) P5.6 U1.F3
JTG1_TMS: JP4.2(S2) P5.2 U1.H6
JTG1_TRST*: JP6.2(S2) P5.9(N9) R14.2(N2) R15.1 U1.G5
JTG_TCK: JP5.1 P4.4 P8.138 U1.F2
JTG_TDI: P4.8 P8.142 U1.E2
JTG_TDO: JP3.1 JP8.1 P8.140 U1.F4
JTG_TMS: JP4.1 P4.2 P8.136 U1.E3
JTG_TRST*: JP6.1 P4.9(N9) P8.144 R10.2(N2) R13.1 U1.E1
LPDDR4_RESET*: R97.1 R147.1 R150.2(N2) U1.B4
LPDDR4_RESET*_X: R97.2(N2) U3.T11
NVT_VCCB: C66.1 U9.B3
ODT_CA_A: R149.1 U3.G2
ODT_CA_B: R148.1 U3.T2
PA_00/UART0_TXB/FPLL2_DBG_LOCK: P8.188 U1.T5 U29.9
PA_01/UART0_RXB/FPLL3_DBG_LOCK/: P8.190 U1.T1 U29.12
PA_02/UART0_RTSB/FLG0/ETH0_PTPA: P8.192 U1.U3 U29.2
PA_03/UART0_CTSB/FLG1/ETH0_PTPA: P8.194 U1.T3 U29.5
PA_04/UART1_RXB/FPLL0_DBG_LOCK/: P8.200 U1.R4
PA_05/UART1_TXB/FPLL1_DBG_LOCK: P8.198 U1.R2
PA_06/UART1_RTSB/SPI5_RDY/FLG2/: P8.202 U1.P6
PA_07/UART1_CTSB/EMSI0_HOST_REG: P8.204 U1.R5
PA_08/TWI0_SCL/PWM0_AH: P8.152 R137.2(N2) U1.P5
PA_09/TWI0_SDA/PWM0_AL: P8.150(N9) R136.2(N2) U1.R3
PA_10/TWI1_SCL/PWM0_BH: P8.158 R139.2(N2) U1.P2
PA_11/TWI1_SDA/PWM0_BL: P8.156 R138.2(N2) U1.P3
PA_12/TWI2_SCL/PWM0_CH: P8.164 R141.2(N2) U1.R1
PA_13/TWI2_SDA/PWM0_CL: P8.162 R140.2(N2) U1.P4
PA_14/TWI3_SCL/TM0_TMR9/HADC0_E: P8.227 R133.2(N2) U1.P1
PA_15/TWI3_SDA/TM0_TMR10/SPI5_S: P8.225 R132.2(N2) U1.N2
PB_00/TWI4_SCL/TM0_TMR14/SPI0_S: P8.233 R135.2(N2) U1.N5
PB_01/TWI4_SDA/TM0_TMR15/SPI0_S: P8.231 R134.2(N2) U1.N4
PB_02/TWI5_SCL/SPI5_SEL2B: R115.2(N2) U1.M2 U4.23 U16.2 U17.1
PB_03/TWI5_SDA/SPI5_SEL3B: R117.2(N2) U1.L6 U4.22 U16.1(SDA) U17.3
PB_04/MLB0_DAT/TM0_TMR11: P8.172 U1.M5
PB_05/MLB0_SIG/TM0_TMR12: P8.170 U1.N3
PB_06/MLB0_CLK/TM0_TMR13/TM0_CL: P8.168 U1.M4
PB_07/TM0_TMR0/SPI2_SEL4B/FPLL2: P8.23 R41.2(N2) U1.N6
PB_08/TMR1/SPI1_SEL4B/FPLL3_REF: P8.25 U1.L3
PB_09/TM0_TMR2/EMSIO_WP/ETH0_PT: P8.119 U1.M3
PB_10/TM0_TMR3/SPI1_D2: R47.2(N2) U1.K3 U6.C4(WP#/(IO2))
PB_11/TM0_TMR4/SPI1_D3: R48.2(N2) U1.L2 U6.D4
PB_12/TM0_TMR5/SPI5_CLK/PWM0__1: R178.2(N2) U1.M6
PB_12/TM0_TMR5/SPI5_CLK/PWM0_DH: P8.11 R178.1
PB_13/TM0_TMR6/SPI5_CITO/PWM0_D: P8.13 U1.K2
PB_14/TM0_TMR7/SPI5_COTI/PWM0_S: P8.15 U1.L4
PB_15/TM0_TMR8/SPI5_SEL1B/PWM0_: P8.17 U1.L5
PC_00/SPI2_CITO_D1: P8.94 U1.U5
PC_01/SPI2_COTI_D0: P8.96 U1.V4
PC_02/SPI2_D2: P8.98 U1.W1
PC_03/SPI2_D3: P8.100 U1.R6
PC_04/SPI2_CLK/TM0_ACLK1: P8.92 R175.1
PC_04/SPI2_CLK/TM0_ACLK1_X: R175.2(N2) U1.V2
PC_05/SPI2_SEL1B/SPI2_TS*: P8.102 U1.Y1
PC_06/SPI2_SEL2B/ETH0_PTPPPS2/E: P8.104 P8.115 U1.V1
PC_07/SPI2_SEL3B/ETH0_PTPPPS3/E: P8.106 P8.117 U1.T2
PC_08/SPI2_RDY: P8.108 U1.V3
PC_09/SPI0_CLK: P8.112 R61.1
PC_09/SPI0_CLK_X: R61.2(N2) U1.V6
PC_10/SPI0_CITO: P8.114 U1.Y4
PC_11/SPI0_COTI: P8.116 U1.V7
PC_12/SPI0_SEL1B/SPI0_TS*: P8.118 U1.AB3
PC_13/SPI0_RDY: P8.122 U1.AB2
PC_14/SPI0_SEL2B/EMSI0_VDD1_SEL: P8.120 U1.AA3
PC_15/SPI1_CLK/TRACE0_CLK/TM0_1: R62.2(N2) U1.W3
PC_15/SPI1_CLK/TRACE0_CLK/TM0_A: P8.1 R43.1 R62.1
PD_00/SPI1_CITO/TRACE0_D00: P8.3 R49.2(N2) U1.AA4
PD_01/SPI1_COTI/TRACE0_D01: P8.5 U1.Y2 U6.D3
PD_02/SPI1_SEL1B/TRACE0_D02/SPI: P8.7 R44.2(N2) U1.T6 U6.C2
PD_03/SPI1_RDY/TRACE0_D03: P8.9 U1.W2
PD_04/SPI1_SEL2B/SMSI0_SD_VDD1_: P8.21 U1.AA1
PD_05/SPI1_SEL3B/EMSIO_UHS1_SWV: R155.2(N2) R156.1 U1.W5 U9.E3
PD_06/CAN0_RX/TM0_AC12: P8.178 U1.U2
PD_07/CAN0_TX: P8.176 U1.U4
PD_08/CAN1_RX/TM0_AC14: P8.184 U1.U1
PD_09/CAN1_TX: P8.182 U1.T4
PD_10/XSPI0_CITO/XSPIO_D1: R32.2(N2) R145.2(N2) TP14.1(N1) U1.E22
PD_11/XSPI0_COTI_D0/XSPI0_D0: R28.2(N2) TP12.1(N1) U1.E21
PD_12/XSPI0_D2: R33.2(N2) TP10.1(N1) U1.H19
PD_13/XSPI0_D3: R29.2(N2) TP8.1(N1) U1.G20
PD_14/XSPI0_CLK/TM0_ACLK4: R19.1 R23.1 R63.1 TP4.1(N1)
PD_14/XSPI0_CLK/TM0_ACLK4_X: R63.2(N2) U1.F21
PD_15/XSPI0_CLKB: R21.1 R25.1 TP6.1(N1) U1.F22
PE_00/XSPI0_D4/TM0_ACLK4: R30.2(N2) TP13.1(N1) U1.G21
PE_01/XSPI0_D5: R34.2(N2) TP15.1(N1) U1.J19
PE_02/XSPI0_D6: R31.2(N2) TP9.1(N1) U1.J18
PE_03/XSPI0_D7: R35.2(N2) TP11.1(N1) U1.G22
PE_04/XSPI0_DQSB_RWDS*: R27.2(N2) R38.2(N2) R40.1 TP7.1(N1) U1.H20
PE_05/XSPI0_SEL1*: R18.2(N2) R22.1 TP3.1(N1) U1.K19
PE_06/XSPI0_SEL2B/SMSI0_LED_CNT: R20.2(N2) R24.1 TP5.1(N1) U1.K17
PE_07/XSPI1_CITO_D1: P8.6 U1.H21
PE_08/XSPI1_COTI_DO: P8.4 U1.H22
PE_09/XSPI1_D2: P8.8 U1.K18
PE_10/XSPI1_D3: P8.10 U1.L19
PE_11/XSPI1_CLK*: P8.24 R144.2(N2)
PE_12/XSPI1_CLK/FPLL2_REF_CLK: P8.26 R177.2(N2)
PE_13/XSPI1_D4: P8.12 U1.L18
PE_14/XSPI1_D5: P8.14 U1.M18
PE_15/XSPI1_D6: P8.16 U1.J22
PF_00/XSPI1_D7: P8.18 U1.K20
PF_01/XSPI1_DQS_RWDS*: P8.2 U1.M17
PF_02/XSPI1_SEL1B: P8.20 U1.M19
PF_03/XSPI1_SEL2B/EMSI0_CD/TM0_: P8.22 R60.1 U1.L20
PF_04/LP0_CLK/FPLL_REF_CLK: P8.253 R152.2(N2)
PF_04/LP0_CLK/FPLL_REF_CLK_X: R152.1 U1.G2
PF_05/LP0_ACK/TM0_ACI13: P8.255 U1.H1
PF_06/LP0_D0: P8.257 U1.H3
PF_07/LP0_D1: P8.259 U1.H2
PF_08/LP0_D2: P8.261 U1.J4
PF_09/LP0_D3: P8.263 U1.F1
PF_10/LP1_CLK: P8.267 R151.2(N2)
PF_10/LP1_CLK_X: R151.1 U1.G3
PF_11/LP1_ACK: P8.269 U1.G1
PF_12/LP1_D0: P8.271 U1.K5
PF_13/LP1_D1: P8.273 U1.J5
PF_14/LP1_D2: P8.275 U1.G4
PF_15/LP1_D3: P8.277 U1.H4
PG_00/ETH0_MDC: P8.125 U1.W13
PG_01/ETH0_MDIO: P8.123 U1.V14
PG_02/ETH0_RXD0: P8.77 U1.Y13
PG_03/ETH0_RXD1: P8.79 U1.AA13
PG_04/ETH0_RXCLK_REFCLK: P8.87 U1.W12
PG_05/ETH0_RXCTL_RXDV: P8.99 U1.V13
PG_06/ETH0_TXD0: P8.89 U1.Y12
PG_07/ETH0_TXD1: P8.91 U1.AA12
PG_08/ETH0_RXD2: P8.81 U1.AB13
PG_09/ETH0_RXD3: P8.83 U1.AB12
PG_10/ETH0_TXCTL_TXEN: P8.103 U1.Y11
PG_11/ETH0_TXCLK: P8.101 U1.AA11
PG_12/ETH0_TXD2: P8.93 U1.AB11
PG_13/ETH0_TXD3: P8.95 U1.W11
PG_14/ETH0_CRS: P8.237 U1.V10
PG_15_ETH0_RX_ER: P8.239 U1.AA10
PH_00/ETH0_COL: P8.241 U1.W10
PH_01/ETH0_PHY_INT: P8.75 U1.V9
PH_02/ETH0_PTPCLKIN0: P8.105 U1.Y10
PH_03/ETH0_PTPAUXIN0: P8.107 U1.Y9
PH_04/ETH0_PTPPPS1: P8.113 U1.AB10
PH_05/ETH0_PTPPPS0: P8.111 U1.W9
PH_06/UART2_RXB/TM0_ACI3: P8.210 U1.J2
PH_07/UART2_TXB: P8.208 U1.J3
PH_08/UART2_RTSB: P8.212 U1.K4
PH_09/UART2_CTSB: P8.214 U1.K6
PH_10/USB0_STP: R205.1 U1.AB7
PH_11/USB0_D7: R194.2(N2) U1.AA9
PH_12/USB0_D6: R195.2(N2) U1.AB9
PH_13/USB0_D5: R196.2(N2) U1.AB6
PH_14/USB0_D4: R197.2(N2) U1.AA6
PH_15/USB0_NXT: R202.2(N2) U1.AB8
PI_00/USB0_DIR: R203.2(N2) U1.AA7
PI_01/USB0_D3: R198.2(N2) U1.AA8
PI_02/USB0_D2: R199.2(N2) U1.Y8
PI_03/USB0_D1: R200.2(N2) U1.Y7
PI_04/USB0_D0: R201.2(N2) U1.W7
PI_05/USB0_CLK: R64.1 R65.1 U1.W8
PWR_RESET: R124.1 U16.3
SD_CARD_EN*: U4.6 U7.15 U8.15
SYS_CLKIN0: R114.2(N2) R142.2(N2) U1.K1
SYS_CLKOUT: TP26.1(N1) U1.L17
SYS_FAULT: DS10.A(P) R67.1 TP25.1(N1) U1.C22
SYS_FAULT*: P8.276 R7.2(N2) R8.2(N2) TP1.1(N1) U1.G19
SYS_HWRST*: R17.2(N2) R157.1 R159.2(N2) R160.2(N2) U1.J17 U4.20 U5.A2 U5.A4 U6.A4 U21.8
SYS_RESOUT*: R9.2(N2) TP2.1(N1) U1.E20
SYS_XTAL0: R143.1 U1.M1
TARGET_RESET*: JP1.1 P8.146 P8.274 R5.1 R123.2(N2) U18.2
UART0_EN*: R81.2(N2) R82.1 U4.7 U29.10 U29.13
UART0_FLOW_EN*: R83.2(N2) R84.1 U4.8 U29.1 U29.4
UART_3V3_IO: C91.1 C92.1 C93.1 DS7.A(P) DS8.A(P) R87.1 R88.1 R89.1 TP18.1(N1) U13.14(VCCB) U14.6
UNNAMED_7_CAP_I120_N1: C257.1 D8.C P3.A4 P3.A9 P3.B4 P3.B9(N9) R210.1
UNNAMED_7_CAP_I130_N1: C258.1 P3.SH1 P3.SH2 P3.SH3 P3.SH4 P3.SH5 P3.SH6 R211.1
UNNAMED_7_CN2P_I131_N2: R212.1 S1.1B(N2)
UNNAMED_7_CN24PAB2GND6SHLD_I123: D6.3 P3.A5 R208.1
UNNAMED_7_CN24PAB2GND6SHLD_I126: D6.1 P3.B5 R209.1
UNNAMED_7_ICMIC20X5_I8_EN: R103.1 R193.2(N2) R221.2(N2) U23.1
UNNAMED_7_ICUSB331X_I85_DATA0: R201.1 U22.16
UNNAMED_7_ICUSB331X_I85_DATA1: R200.1 U22.15
UNNAMED_7_ICUSB331X_I85_DATA2: R199.1 U22.14
UNNAMED_7_ICUSB331X_I85_DATA3: R198.1 U22.13
UNNAMED_7_ICUSB331X_I85_DATA4: R197.1 U22.11
UNNAMED_7_ICUSB331X_I85_DATA5: R196.1 U22.10
UNNAMED_7_ICUSB331X_I85_DATA6: R195.1 U22.9
UNNAMED_7_ICUSB331X_I85_DATA7: R194.1 U22.8
UNNAMED_7_ICUSB331X_I85_DIR: R203.1 U22.19
UNNAMED_7_ICUSB331X_I85_NXT: R202.1 U22.18
UNNAMED_7_ICUSB331X_I85_RBIAS: R206.1 U22.24
UNNAMED_7_ICUSB331X_I85_STP: R205.2(N2) U22.20
UNNAMED_7_ICUSB331X_I85_VBUS: R218.2(N2) U22.2
UNNAMED_7_RES_I185_N1: R217.1 Y4.3
USB_DM: D1.3 P2.A7 P2.B7 U14.5
USB_DP: D1.4 P2.A6 P2.B6 U14.4
USB_PHY_CLKOUT: R65.2(N2) U22.12
USB_PHY_DM: P3.A7 P3.B7 U22.5
USB_PHY_DP: P3.A6 P3.B6 U22.6
USB_PHY_ID: R39.2(N2) S1.1A U22.1
USB_PHY_REFCLK: R64.2(N2) R217.2(N2) U22.23
USB_PHY_RESET*: R207.1 U4.5 U22.22
USB_PHY_VBUS: C244.1 C246.P R210.2(N2) R218.1 U23.6 U23.8(OUT2)
USB_PHY_VBUS_EN: R193.1 U22.7
USB_TYPEC: C86.1 C94.1 D1.1 D3.C D7.A(P) E1.1 P2.A4 P2.A9 P2.B4 P2.B9(N9) R163.1

Pads without a net: D1 6; D2 4 5; D6 4 5; P2 A2 A3 A8 A10 A11 B2 B3 B8 B10 B11; P3 A2 A3 A8 A10 A11 B2 B3 B8 B10 B11; P4 7; P5 7; P8 19 135 137 139 141 143 147 149 151 153 155 159 161 163 165 167 171 173 175 177 179 183 185 187 189 195 197 199 201 205 207 209 211 215 217 218 219 220 221 222 224 226 228 230 232 234 236 240 242 244 246 248 250 252 254 256 258 270; U2 12 15; U3 A1 A2 A8 A11 A12 AA1 AA12 AB1 AB2 AB11 AB12 B1 B12 G11 K5 K8 N5 N8; U4 1 2 3 4 9 10 11 12 13 14 15 24; U5 A5 B5 C5; U6 A2 A3 A5 B1 B5 C1 C3 C5 D1 D5 E1 E2 E3 E4 E5; U9 E2; U10 A1 A2 A7 A8 A9 A10 A11 A12 A13 A14 B1 B7 B8 B9 B10 B11 B12 B13 B14 C1 C3 C5 C7 C8 C9 C10 C11 C12 C13 C14 D1 D2 D3 D4 D12 D13 D14 E1 E2 E3 E5 E8 E9 E10 E12 E13 E14 F1 F2 F3 F10 F12 F13 F14 G1 G2 G3 G10 G12 G13 G14 H1 H2 H3 H12 H13 H14 J1 J2 J3 J12 J13 J14 K1 K2 K3 K6 K7 K10 K12 K13 K14 L1 L2 L3 L12 L13 L14 M1 M2 M3 M7 M8 M9 M10 M11 M12 M13 M14 N1 N3 N6 N7 N8 N9 N10 N11 N12 N13 N14 P1 P2 P7 P8 P9 P10 P11 P12 P13 P14; U13 6 9; U14 1 2 10 11 12 13 14 15 16 17 20 21 22 27 28; U16 5 15 22 23 24 25 27; U19 1; U23 2 4 5

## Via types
v1: diameter 0.305, hole 0.152, TOP to BOTTOM, 905 vias
v2: diameter 0.508, hole 0.254, TOP to BOTTOM, 826 vias
v3: diameter 0.432, hole 0.203, TOP to L3_SIG1, 30 vias
v4: diameter 0.635, hole 0.305, TOP to BOTTOM, 3 vias
v5: diameter 0.432, hole 0.203, L10_SIG4 to BOTTOM, 30 vias

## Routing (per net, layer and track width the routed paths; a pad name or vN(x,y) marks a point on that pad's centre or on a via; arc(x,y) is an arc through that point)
1V8_LDO0:
  vias: v2(6.3,31.34) v2(6.81,31.34) v2(7.32,31.34)
1V8_LDO2:
  vias: v2(9.35,31.34) v2(9.86,31.34) v2(10.36,31.34)
1V8_LDO3:
  vias: v2(12.9,31.34) v2(13.41,31.34) v2(13.92,31.34)
3V3: length 25.1
  TOP w0.203: U9.A3 17.04,5.83 C61.2
  TOP w0.305: v1(36.92,9.71) 37.72,8.91 C67.2 37.84,8.91 C63.1 39.22,10.29 39.22,10.31 C65.2 39.22,10.36 39.22,10.41 v1(38.42,11.21)
  TOP w0.381: C61.2 17.36,6.9 v2(17.35,6.91)
  TOP w0.508: P6.4 v2(26.4,6.21) ; v2(58.5,14.27) 61.78,14.27 62.43,14.92 R221.1
  BOTTOM w0.203: U2.11 5.68,44.87 5.22,45.33 v2(5.22,46.65)
  BOTTOM w0.229: U10.K9 v1(38.42,11.21) U10.J10 ; U10.F5 v1(36.92,9.71) U10.E6
  BOTTOM w0.508: v2(5.22,46.65) R116.1 R120.1 ; R124.2 v2(8.33,34.27)
  vias: v2(2.68,28.65) v2(2.78,36.63) v2(2.78,35.99) v2(3.42,36.63) v2(3.39,35.99) v2(3.78,33.45) v2(3.78,32.82) v2(4.41,33.45) v2(4.41,32.82) v2(9.44,36.63) v2(9.46,35.99) v2(9.8,23.16) v2(9.8,22.53) v2(10.07,36.63) v2(10.07,35.99) v2(10.44,23.16) v2(10.44,22.53) v2(13.54,26.91) v2(13.54,26.28) v2(14.17,26.91) v2(14.17,26.28) v2(57.73,14.27)
DGND: length 672.4
  TOP w0.14: U1.L14 v1(38.95,50.22) ; U1.AB16 v1(37.37,58.99) ; U1.D22 v1(32.55,43.82) ; U1.T9 v1(43.75,54.22) ; U1.H11 v1(42.15,47.82) ; U1.D4 v1(47.75,43.82) ; U1.T13 v1(39.75,54.22) ; P8.166 v1(52.25,66.55) ; U1.B21 v1(33.35,42.22) ; U1.L12 v1(40.55,50.22) ; P8.134 v1(44.25,66.55) ; U1.W14 v1(38.97,56.59) ; U1.E18 v1(35.75,44.62) ; U1.N12 v1(40.55,51.82) ; U1.L10 v1(42.15,50.22) ; U1.J10 v1(42.15,48.62) ; U1.AA17 v1(36.57,58.19) ; U1.B17 v1(36.55,42.22) ; U1.B2 v1(49.35,42.22) ; U1.D12 v1(40.55,43.82) ; U1.T7 v1(45.35,54.22) ; U1.N22 v1(32.55,51.82) U1.P22 ; U1.A11 v1(42.15,41.42) ; v1(46.13,57.39) U1.Y6 U1.W6 ; U1.J7 v1(45.35,47.82) ; U1.F13 v1(39.75,46.22) ; U1.N14 v1(38.95,51.82) ; U1.U6 v1(46.15,55.02) ; U1.H8 v1(44.55,47.82) ; U1.T16 v1(37.35,54.22) ; U1.V17 v1(36.57,55.79) ; U1.H10 v1(42.95,47.82) ; P8.50 23.15,68.23 23.15,66.68 23.06,66.6 23.06,65.33 v1(23,65.27) ; U1.F17 v1(36.55,45.42) ; U1.W4 v1(47.75,56.62) U1.Y3 ; U1.H17 v1(36.55,47.02) ; U1.N9 v1(43.75,51.82) ; U1.H12 v1(40.55,47.82) ; U1.J13 v1(39.75,48.62) ; U1.V18 v1(35.75,55.82) ; U1.AA21 v1(33.35,58.22) ; U1.N13 v1(39.75,51.82) ; U1.D8 v1(44.55,43.82) ; U1.C3 v1(48.55,43.02) ; U1.N1 v1(50.15,51.82) ; U1.E5 v1(46.95,44.62) ; P8.148 v1(47.75,66.55) ; U1.W18 v1(35.77,56.59) ; P8.196 v1(59.75,66.55) ; U1.U17 v1(36.55,55.02) ; U1.N16 v1(37.35,51.82) ; U1.H13 v1(39.75,47.82) ; U1.A22 v1(32.55,41.42) ; U1.AB1 v1(50.15,59.02) ; U1.L13 v1(39.75,50.22) ; U1.AB17 v1(36.57,58.99) ; U1.R7 v1(45.35,53.42) ; U1.Y17 v1(36.57,57.39) ; U1.C16 v1(37.35,43.02) ; U1.AB4 v1(47.73,58.99) ; U1.W17 v1(36.57,56.59) ; U1.V16 v1(37.37,55.79) ; U1.J1 v1(50.15,47.82) ; U1.J16 v1(37.35,48.62) ; U1.AA14 v1(38.97,58.19) ; U1.D17 v1(36.55,43.82) ; U1.V8 v1(44.53,55.79) ; U1.H15 v1(38.15,47.82) ; U1.W19 v1(34.95,56.62) ; U1.L7 v1(45.35,49.42) ; U1.D6 v1(46.15,43.82) ; U1.V15 v1(38.17,55.79) ; U1.D19 v1(34.95,43.82) ; U1.N11 v1(42.15,51.82) ; U1.N7 v1(45.35,51.82) ; P8.160 v1(50.75,66.55) ; U1.T11 v1(42.15,54.22) ; U1.C18 v1(35.75,43.02) ; U1.Y5 v1(46.93,57.39) ; U1.V5 v1(46.95,55.82) ; U1.AA16 v1(37.37,58.19) ; U1.C7 v1(45.35,43.02) ; U1.W16 v1(37.37,56.59) ; 28.75,66.57 P8.72 ; U1.Y20 v1(34.15,57.42) ; U1.G16 v1(37.35,46.22) ; U1.N10 v1(42.95,51.82) ; U1.L9 v1(43.75,50.22) ; P8.180 v1(55.75,66.55) ; U1.AA15 v1(38.17,58.19) ; U1.L11 v1(41.35,50.22) ; U1.Y14 v1(38.97,57.39) ; U1.H9 v1(43.75,47.82) ; U1.AA2 v1(49.35,58.22) ; U1.W15 v1(38.17,56.59) ; U1.AB14 v1(38.97,58.99) ; U1.L16 v1(37.35,50.22) ; v1(45.35,46.22) U1.F6 ; U14.3 v2(68.06,20.29) ; U1.AB22 v1(32.55,59.02) ; U1.D15 v1(38.15,43.82) ; U1.B6 v1(46.15,42.22) ; U1.C1 v1(50.15,43.02) ; U1.Y15 v1(38.17,57.39) ; U1.F11 v1(42.15,46.22) ; U1.R16 v1(37.35,53.42) ; U1.AA5 v1(46.93,58.19) ; U1.A1 v1(50.15,41.42) ; U1.C5 v1(46.95,43.02) ; U1.AB15 v1(38.17,58.99) ; U1.C20 v1(34.15,43.02) ; U1.Y16 v1(37.37,57.39) ; U1.H14 v1(38.95,47.82) ; U1.AB5 v1(46.93,58.99) ; U1.T15 v1(38.15,54.22) ; P8.154 v1(49.25,66.55)
  TOP w0.203: P8.90 33.25,66.84 33.07,66.66 v1(33.07,65.84) ; v1(37.99,66.58) 38.25,66.84 P8.110 ; v1(17.22,65.96) 17.35,66.09 17.38,66.09 17.6,66.31 17.6,66.7 17.75,66.84 P8.28
  TOP w0.254: P8.174 v1(54.25,66.55)
  TOP w0.305: C16.1 41.99,37.48 v3(41.95,37.52) ; v2(55.9,48.73) 55.68,48.95 54.42,48.95 C24.2 ; P8.206 v1(62.25,66.55) ; P2.GND1 P2.B12 66.06,9.32 P2.A1 66.06,12.43 D3.A ; v2(42.11,6.4) 42.77,5.75 U4.19 ; P8.216 v1(64.75,66.47) ; C95.2 75.9,6.79 75.9,6.27 ; P2.GND2 P2.B1 71.56,9.32 P2.A12 71.56,11.73 C94.2 ; D8.A 51.91,12.43 P3.A1 51.91,9.32 P3.B12 P3.GND1 ; P8.186 v1(57.25,65.84) ; P3.GND2 P3.B1 57.41,9.32 P3.A12 57.41,11.73 C257.2 ; C190.2 v1(45.29,60.57) ; C18.1 40.72,36.93 41,37.22 v3(41,37.52) ; 77.75,66.54 P8.268 ; v2(54.31,49.82) U1.L1 ; P8.260 v1(75.75,65.96)
  TOP w0.381: v2(15.32,6.91) 15.32,6.9 C62.1 ; v2(15.06,1.26) 15.07,1.27 R156.2 ; C66.2 v2(19.5,3.71) ; C61.1 18.36,6.9 v2(18.36,6.91) ; 34.34,60.64 C187.2
  TOP w0.508: 57.8,49.98 v2(57.8,50.93) ; v2(57.8,50.93) 58.65,50.93 ; v2(57.8,50.93) 57.8,51.89 ; v2(57.8,50.93) 56.94,50.93 ; 56.29,45.8 Y2.2 55.7,46.43 ; 20.59,40.69 C54.1 ; C54.1 21.14,40.11 ; C54.1 21.16,40.71 R42.2 ; C258.2 62.41,6.91 ; C258.2 61.87,6.32 ; C258.2 v2(61.87,7.62) ; 72.47,48.94 P12.6 ; P12.6 72.47,47.17 ; P12.6 74.24,48.94 ; P12.6 74.24,47.17 ; S4.1 74.55,52.92 ; S4.1 73.24,51.96 ; S4.1 73.24,53.87 ; S4.1 71.93,52.92 ; C37.1 55.35,41.71 ; C37.1 54.81,42.29 ; C37.1 54.81,41.12 ; 35.12,60.62 C187.2 34.36,60.05 v2(34.54,59.87) ; C192.2 v2(29.04,54.57) ; R211.2 v2(62.47,9.64) ; R211.2 61.82,8.69 ; R211.2 62.47,7.94 ; C241.1 v2(56.44,43.1) ; D1.5 v2(66.59,16.26) ; P6.9_1 35.32,1.35 ; P6.9_1 33.41,1.35 ; P6.9_1 v2(34.36,2.76) ; C194.2 v2(29.04,57.58) ; C194.2 29.79,58.17 ; C194.2 29.79,57 ; C206.2 29.8,59.56 ; C206.2 29.8,58.39 ; C206.2 29.26,58.98 ; v2(21.15,52.91) C58.1 ; 28.27,33.65 R12.2 ; R12.2 v2(27.52,34.22) ; R12.2 28.89,34.22 ; C188.2 v2(53.77,53.99) ; C188.2 53.02,53.41 ; C188.2 53.02,54.58 ; R86.2 v2(74.78,20.95) ; 40.5,17.69 C5.2 ; C5.2 v2(41.48,16.66) ; C5.2 42.46,17.69 ; C64.1 37.37,5.51 ; C64.1 36.83,6.1 ; C64.1 36.83,4.93 ; R103.2 63.05,23.92 v2(63.35,23.92) ; U17.5 65.64,62.22 ; U17.5 66.65,61.71 ; U17.5 65.64,61.2 ; U17.5 64.62,61.71 ; C96.2 v2(75.79,62.51) ; P6.6 v2(24.2,6.14) ; C244.2 v2(48.57,19.35) ; 75.97,8.69 R91.2 ; R91.2 77.27,8.69 ; R91.2 76.62,7.94 ; R91.2 v2(76.62,9.64) ; 55.04,48.73 v2(55.9,48.73) ; v2(55.9,48.73) 56.75,48.73 ; v2(55.9,48.73) 55.9,49.69 ; 53.17,30.42 R212.2 52.6,31.04 ; 27.9,42.65 C33.1 ; C33.1 27.9,43.82 ; C33.1 27.35,43.23 ; P5.5 80.12,53.14 ; 15.07,2.71 R156.2 14.5,2.08 ; C89.2 v2(74.78,19.91) ; C32.1 v2(9.47,6.53) ; C32.1 10.37,5.94 ; C32.1 10.37,7.11 ; S4.2 65.64,52.92 ; S4.2 63.02,52.92 ; S4.2 64.33,53.87 ; C14.2 38.77,17.69 ; C14.2 v2(37.8,16.66) ; C14.2 36.82,17.69 ; P12.5 71.7,48.94 ; P12.5 69.93,47.17 ; P12.5 71.7,47.17 ; P12.5 69.93,48.94 ; 73.92,62.77 U15.5 74.93,62.27 ; 20.26,2.35 P6.9_2 ; P6.9_2 21.21,3.56 ; P6.9_2 22.17,2.35 ; P6.9_2 21.21,0.94 ; C146.2 v2(45.03,16.66) ; C146.2 44.06,17.69 ; C146.2 46.01,17.69 ; 25.91,37.52 R67.2 ; R67.2 27.16,37.52 ; R67.2 26.54,36.95 ; R84.2 v2(76.28,26.98) ; R84.2 76.9,26.08 ; R84.2 75.65,26.08 ; C53.2 41.35,3.1 ; C71.1 v2(36.91,16.59) ; C93.2 v2(69.93,18.31) ; 64.31,60.76 U17.2 62.28,60.76 ; C242.2 67.97,61.26 ; C242.2 67.39,61.8 ; C242.2 66.8,61.26 ; C246.N v2(59.95,15.27) ; C95.2 v2(76.01,7.62) ; R42.2 20.54,41.71 ; R42.2 21.78,41.71 ; P4.3 80.12,37.77 ; C191.2 53.02,56.18 ; C191.2 53.57,55.6 ; C191.2 53.02,55.01 ; 53.72,49.06 C24.2 ; C24.2 54.89,49.06 ; C24.2 v2(54.31,49.82) C25.2 ; C243.2 v2(48.57,21.51) ; 60.6,23.29 U23.3 57.91,23.29 ; v2(78.74,29.27) 78.74,30.16 78.23,30.67 R82.2 ; 70.56,61.32 U15.2 ; D1.2 v2(71.03,16.26) ; C185.2 v2(51.27,58.87) ; 9.09,2.61 U19.3 ; U19.3 8.23,3.16 ; U19.3 9.94,3.16 ; v2(27.9,48.31) v2(27.9,47.17) ; v2(27.9,48.31) 27.9,48.93 ; v2(27.9,48.31) 27.33,48.31 ; C184.2 34.34,60.64 ; v2(48.07,59.84) C189.2 48.06,60.57 C190.2 ; P4.5 80.12,39.04 ; P5.3 80.12,51.87 ; v2(80.91,65.27) v2(80.91,66.15) ; C186.2 v2(51.27,57.2) ; C69.1 v2(35.76,16.59) ; C55.2 v2(40.21,2.87) ; C193.2 v2(29.04,56.07)
  L2_GND w0.508: P12.6 74.24,48.94 ; P12.6 74.24,47.17 ; P12.6 72.47,47.17 ; P12.6 72.47,48.94 ; 65.47,9.81 P2.B12 65.47,8.74 ; P5.3 80.12,51.87 ; 51.32,9.81 P3.B12 51.32,8.74 ; P12.5 71.7,48.94 ; P12.5 71.7,47.17 ; P12.5 69.93,47.17 ; P12.5 69.93,48.94 ; 58,8.74 P3.B1 58,9.81 ; P4.5 80.12,39.04 ; 72.14,8.74 P2.B1 72.14,9.81 ; P4.3 80.12,37.77 ; P5.5 80.12,53.14
  L3_SIG1 w0.508: 58,8.74 P3.B1 58,9.81 ; 72.14,9.81 P2.B1 72.14,8.74 ; 69.93,48.94 P12.5 69.93,47.17 ; 51.32,9.81 P3.B12 51.32,8.74 ; P4.5 80.12,39.04 ; P4.3 80.12,37.77 ; 65.47,9.81 P2.B12 65.47,8.74
  L4_GND w0.508: P4.3 80.12,37.77 ; 51.32,8.74 P3.B12 51.32,9.81 ; 65.47,9.81 P2.B12 65.47,8.74 ; 69.93,47.17 P12.5 ; P12.5 71.7,48.94 ; P12.5 71.7,47.17 ; P12.5 69.93,48.94 ; 72.14,9.81 P2.B1 72.14,8.74 ; 58,9.81 P3.B1 58,8.74 ; P5.5 80.12,53.14 ; 72.47,47.17 P12.6 ; P12.6 72.47,48.94 ; P12.6 74.24,47.17 ; P12.6 74.24,48.94 ; P4.5 80.12,39.04 ; P5.3 80.12,51.87
  L5_SIG2 w0.508: P5.5 80.12,53.14 ; 72.47,47.17 P12.6 ; P12.6 74.24,48.94 ; P12.6 72.47,48.94 ; P12.6 74.24,47.17 ; P12.5 71.7,48.94 ; P12.5 69.93,48.94 ; P12.5 71.7,47.17 ; P12.5 69.93,47.17 ; P4.5 80.12,39.04 ; P5.3 80.12,51.87 ; P4.3 80.12,37.77
  L8_SIG3 w0.508: 51.32,9.81 P3.B12 51.32,8.74 ; 72.47,48.94 P12.6 ; P12.6 74.24,47.17 ; P12.6 72.47,47.17 ; P12.6 74.24,48.94 ; 72.14,8.74 P2.B1 72.14,9.81 ; 65.47,8.74 P2.B12 65.47,9.81 ; P5.3 80.12,51.87 ; P4.3 80.12,37.77 ; 69.93,47.17 P12.5 ; P12.5 71.7,48.94 ; P12.5 71.7,47.17 ; P12.5 69.93,48.94 ; P5.5 80.12,53.14 ; 58,8.74 P3.B1 58,9.81 ; P4.5 80.12,39.04
  L9_GND w0.508: 72.14,9.81 P2.B1 72.14,8.74 ; 65.47,8.74 P2.B12 65.47,9.81 ; P4.5 80.12,39.04 ; 58,9.81 P3.B1 58,8.74 ; 69.93,47.17 P12.5 ; P12.5 71.7,48.94 ; P12.5 71.7,47.17 ; P12.5 69.93,48.94 ; 51.32,9.81 P3.B12 51.32,8.74 ; P5.3 80.12,51.87 ; 72.47,48.94 P12.6 ; P12.6 74.24,47.17 ; P12.6 72.47,47.17 ; P12.6 74.24,48.94 ; P5.5 80.12,53.14 ; P4.3 80.12,37.77
  L10_SIG4 w0.508: P5.3 80.12,51.87 ; P12.6 74.24,47.17 ; P12.6 72.47,47.17 ; P12.6 74.24,48.94 ; P12.6 72.47,48.94 ; P4.5 80.12,39.04 ; P5.5 80.12,53.14 ; P12.5 71.7,47.17 ; P12.5 71.7,48.94 ; P12.5 69.93,47.17 ; P12.5 69.93,48.94 ; P4.3 80.12,37.77
  L11_GND w0.508: P4.3 80.12,37.77 ; P12.5 71.7,48.94 ; P12.5 69.93,48.94 ; P12.5 69.93,47.17 ; P12.5 71.7,47.17 ; 72.47,47.17 P12.6 ; P12.6 74.24,47.17 ; P12.6 74.24,48.94 ; P12.6 72.47,48.94 ; P5.5 80.12,53.14 ; P4.5 80.12,39.04 ; P5.3 80.12,51.87
  BOTTOM w0.14: v2(24.52,18.34) 24.77,18.09 U7.7 ; v2(28.17,19.7) 27.85,19.38 U7.12 ; U7.8 25.45,18.49 24.89,19.05 v2(24.52,19.05) ; U8.6 21.55,10.2 v2(21.29,9.95) ; U7.10 27.05,19.75 v2(26.37,20.43) ; v2(26.32,19.67) 26.65,19.34 U7.9 ; v2(28.14,20.43) 27.45,19.75 U7.11 ; v1(28.52,66.55) 28.52,66.6 28.5,66.63 P8.71 ; v2(24.53,17.44) 24.79,17.69 U7.6 ; 37.42,10.21 v1(37.42,10.21) ; P8.73 v1(29,66.55) ; v1(43.75,50.22) 43.75,50.08 C215.2 ; P8.85 v1(32,66.55) ; 37.92,10.71 v1(37.92,10.72)
  BOTTOM w0.203: v1(37.99,66.58) 38,66.59 P8.109 ; P8.49 v1(23,65.27) ; P8.97 35,66.33 34.75,66.09 34.52,66.09 v1(34.5,66.07) ; P8.121 41,66.5 ; P8.203 61.5,66.65 61.59,66.55 v1(62.25,66.55) ; P8.27 17.5,66.74 17.6,66.63 17.6,66.31 17.25,65.96 v1(17.22,65.96)
  BOTTOM w0.229: U10.P4 v1(35.92,14.11) ; U10.J5 v1(36.91,11.21) ; U10.P6 v1(36.92,14.11) ; U10.G5 37.42,10.21 ; v2(37.17,6.7) 36.92,6.95 U10.A6 ; U10.K8 v1(37.92,10.72) ; U10.H10 37.92,10.71 ; U10.E7 v1(37.42,10.21)
  BOTTOM w0.305: U3.G1 v1(38.75,34.7) 38.75,35.04 37.93,35.86 C21.1 37.93,37.24 ; U3.E8 v1(36.8,29.1) ; v1(35.5,34.7) U3.C1 36.15,33.9 U3.D2 ; P8.145 47,66.67 47.12,66.55 v1(47.75,66.55) ; U3.W9 v1(45.9,28.3) U3.V8 v1(45.9,29.1) ; U3.W4 v1(46.55,31.5) U3.Y5 v1(47.2,30.7) ; U3.G5 v1(38.75,30.7) ; U3.J1 40.05,34.7 40.05,35.64 39.84,35.86 C22.1 39.84,37.24 ; U3.V5 v1(45.9,30.7) ; v1(66.5,66.55) P8.223 ; P8.251 73.5,66.49 v1(73.48,66.47) ; U3.J10 U3.K9 v1(40.7,28.3) ; P8.235 v1(69.5,66.42) ; U21.1 66.57,55.41 66.88,55.72 v2(66.88,56.18) ; U18.3 71.79,55.28 ; U18.3 71.07,54.86 ; U18.3 70.35,55.28 ; U3.T8 v1(43.95,29.1) ; 42.87,37.24 C23.1 42.87,35.73 42.65,35.51 v1(42.65,34.7) U3.P1 ; v1(35.5,29.1) U3.C8 36.15,28.3 U3.D9 ; U3.T5 v1(43.95,30.7) ; v1(42,33.9) U3.N2 v1(42.65,33.1) U3.P3 v1(42.65,32.3) U3.N4 U3.K4 v1(40.05,32.3) U3.J3 ; U3.G12 v1(38.1,25.1) ; U3.W11 46.55,25.9 U3.Y12 v1(47.2,25.1) ; U16.4 v2(10.11,29.75) ; U3.G8 v1(38.75,29.1) ; v2(77.48,66.09) 77,66.58 P8.265 ; U3.G3 v1(38.75,33.1) ; U3.D4 v1(36.15,31.5) U3.C5 35.48,30.67 35.51,30.38 v1(35.53,30.35) ; U3.E5 v1(36.8,30.7) ; U3.A3 v1(34.2,33.1) ; U3.G10 v1(38.1,26.7) ; 73.91,12.17 U13.7 ; U13.7 v2(74.33,13.58) ; U13.7 74.33,11.09 ; v1(48.77,26.72) 48.55,26.72 U3.AB10 ; U3.A10 v1(34.2,26.7) ; U5.C1 17.77,41.33 ; U3.AB3 v1(48.5,33.1) ; 74.33,24.42 U29.7 ; U29.7 73.91,25.5 ; U29.7 v2(74.33,26.91) ; P8.279 80.5,66.53 80.87,66.15 v2(80.91,66.15) 80.91,66.16 81,66.25 P8.281 ; U3.K2 v1(40.7,33.9) ; U3.T12 v1(43.95,25.1) ; U3.E1 36.8,34.8 ; U3.W2 U3.Y1 47.27,34.78 v1(47.22,35.31) ; v1(36.8,35.53) 36.8,35.63 37.03,35.86 C162.1 37.03,37.24 ; v1(35.48,24.61) 35.48,25.07 35.83,25.49 U3.C12 v1(36.15,25.9) U3.D11 ; P8.229 v1(68,66.54) ; v1(57.25,65.84) 57.86,65.84 58.5,66.47 P8.191 ; v1(42,28.3) U3.N9 U3.P10 v1(43.3,26.7) ; U5.B3 v2(21.15,39.83) ; v1(43.95,33.11) U3.T3 ; v1(49.25,66.03) 49.44,66.03 49.45,66.04 49.46,66.04 49.75,66.34 49.75,66.35 50,66.59 P8.157 ; 45.68,37.24 C51.1 45.68,35.74 45.9,35.51 45.9,35.33 v1(45.92,35.31) 45.98,34.79 U3.V1 ; 68.81,2.72 v2(68.81,4.41) ; U3.T1 v1(43.95,34.7) 43.95,35.04 44.77,35.86 C50.1 44.77,37.24 ; U3.V12 v1(46.02,24.87) ; U5.E5 22.65,44.75 ; v2(40.21,39.26) C49.2 41.04,39.87 C115.2 41.41,39.87 C46.2 v2(42.24,39.26) ; R13.2 v2(77.81,44.49) ; 54.66,2.72 v2(54.66,4.41) ; U3.E12 v1(36.8,25.1) ; U3.T10 v1(44.6,26.68) ; U3.AB5 v1(48.5,31.5) ; U16.26 v2(6.96,27.03) ; v1(42.65,25.1) U3.P12 v1(42.65,25.9) U3.N11 U3.K11 v1(40.05,25.9) U3.J12 v1(39.4,25.1) ; U3.AB8 v1(48.5,29.1) ; U3.Y8 v1(47.2,29.1)
  BOTTOM w0.33: U6.B3 v2(21.15,52.91)
  BOTTOM w0.508: 28.87,38.4 v2(29.42,38.4) 29.42,38.99 ; C262.2 v2(61.82,12.5) ; C262.2 62.7,11.91 ; C262.2 62.7,13.08 ; C256.2 v2(57.99,28.61) ; C185.2 52.02,59.45 ; C185.2 52.02,58.28 ; C185.2 v2(51.27,58.87) ; C197.2 v2(24.35,57.84) ; C197.2 25.1,58.42 ; C197.2 25.1,57.25 ; C252.2 C248.2 ; C252.2 v2(58.85,17.32) ; C252.2 C249.2 ; C248.2 C251.2 v2(58.86,15.29) ; C248.2 v2(58.86,16.31) ; 72.14,9.81 P2.B1 72.14,8.74 ; C125.2 v2(71.68,57.84) ; C125.2 70.93,58.42 ; C125.2 70.93,57.25 ; C151.1 v2(44.15,21.42) ; C151.1 44.73,22.16 ; C151.1 43.56,22.16 ; 35.56,22.16 C155.1 ; C155.1 36.73,22.16 ; C155.1 v2(36.14,21.41) ; 50.83,48.95 C27.2 50.24,48.41 ; R51.2 v2(28.55,12.23) ; 25.1,58.78 C195.2 ; C195.2 25.1,59.94 ; C195.2 v2(24.35,59.36) ; C206.2 v2(29.05,58.98) ; C206.2 29.8,59.56 ; C206.2 29.8,58.39 ; C255.2 v2(59,28.61) ; C159.1 v2(30.58,30.66) ; R40.2 v2(19,36.81) ; R45.2 v2(14.74,52.5) ; R6.2 v2(69.24,43.23) ; R6.2 69.93,42.61 ; R6.2 69.93,43.85 ; 31.01,17.49 C59.2 ; C59.2 v2(31.76,18.07) ; C59.2 31.01,18.66 ; R208.2 R209.2 ; 39.5,22.16 C153.1 ; C153.1 v2(40.08,21.41) ; C153.1 40.67,22.16 ; C91.2 v2(80.15,15.93) ; C91.2 79.45,15.39 ; C91.2 78.87,15.93 ; P4.5 80.12,39.04 ; C154.1 v2(38.68,21.41) ; C154.1 38.1,22.16 ; C154.1 39.27,22.16 ; 46.35,60.57 C190.2 ; C190.2 46.93,60.03 ; C190.2 48.06,60.57 C189.2 v2(48.07,59.84) ; 69.93,48.94 P12.5 ; P12.5 69.93,47.17 ; P12.5 71.7,47.17 ; P12.5 71.7,48.94 ; C156.1 v2(30.58,26.72) ; C152.1 42.57,22.16 ; C152.1 v2(41.99,21.41) ; C152.1 41.4,22.16 ; 28.91,42.51 R68.2 ; R68.2 28.91,43.75 ; R68.2 28.34,43.13 ; C26.2 53.07,48.25 ; C26.2 50.96,48.25 ; C26.2 52.02,47.35 ; 64.84,42.61 R1.2 ; R1.2 v2(65.54,43.23) ; R1.2 64.84,43.85 ; C150.1 v2(46.56,21.41) ; C150.1 45.97,22.16 ; C150.1 47.14,22.16 ; 64.84,37.53 R3.2 ; R3.2 64.84,38.77 ; R3.2 v2(65.54,38.15) ; R94.2 R93.2 ; C171.2 29.92,53.39 29.79,53.52 C192.2 ; 51.32,9.81 P3.B12 51.32,8.74 ; v2(34.54,59.87) 34.36,60.05 C187.2 34.34,60.64 C184.2 ; 27.77,10 C60.2 ; C60.2 v2(28.52,10.58) ; C60.2 27.77,11.17 ; 72.47,47.17 P12.6 ; P12.6 74.24,48.94 ; P12.6 72.47,48.94 ; P12.6 74.24,47.17 ; C254.2 C253.2 v2(63.35,23.92) ; P5.3 80.12,51.87 ; 29.79,56.66 C193.2 29.25,56.07 ; 29.79,57 C194.2 ; C194.2 29.25,57.58 ; C194.2 29.79,58.17 ; R2.2 69.93,38.77 ; R2.2 69.93,37.53 ; R2.2 v2(69.24,38.15) ; 13.8,35.87 R19.2 ; R19.2 15.05,35.87 ; R19.2 14.43,35.1 ; 36.83,22.16 C3.1 ; C3.1 38,22.16 ; C3.1 v2(37.41,21.41) ; R21.2 v2(17.26,38.02) ; Y4.2 62.45,16.69 ; Y4.2 60.95,16.69 ; Y4.2 v2(61.7,15.27) ; C98.1 v2(52.13,31.93) ; 22.65,44.75 C57.1 v2(22.65,47.32) ; R50.2 v2(31.78,19.72) ; R50.2 31.01,20.35 ; R50.2 31.01,19.1 ; C137.2 v2(65.35,51.46) ; 52.02,56.62 C186.2 ; C186.2 v2(51.27,57.2) ; C186.2 52.02,57.78 ; C100.1 v2(52.13,30.66) ; C92.2 69.67,22.61 ; C92.2 70.42,21.88 ; C92.2 69.86,21.7 v2(70.71,21.7) 71.65,21.7 C88.2 ; C92.2 68.92,21.88 ; R169.1 v2(1.98,58.34) ; 54.72,54.16 C164.2 ; C164.2 56.68,54.16 ; C164.2 55.7,54.99 ; 58,9.81 P3.B1 58,8.74 ; 29.4,59.65 C198.2 ; C198.2 29.4,61.61 ; C198.2 v2(28.37,60.63) ; C101.1 v2(52.13,26.72) ; R166.1 v2(6.55,60.5) ; 17.77,41.33 16.51,41.33 C56.1 v2(15.71,41.33) ; C90.2 v2(80.15,14.14) ; C157.1 v2(30.58,27.86) ; R170.1 v2(8.37,53.4) ; P4.3 80.12,37.77 ; C238.2 v2(1.2,46.15) ; 65.47,9.81 P2.B12 65.47,8.74 ; R168.1 v2(12.4,58.34) ; 28.87,37.39 v2(29.42,37.39) 29.42,36.8 ; 53.15,36.55 v2(53.15,37.13) 53.7,37.13 ; C250.2 v2(5.99,53.4) ; C161.1 v2(30.58,33.07) ; v2(73.2,12.45) C86.2 ; 53.15,38.74 v2(53.15,38.15) 53.7,38.15 ; R130.2 v2(60.27,54.03) ; C87.2 v2(78.74,29.27) ; R206.2 v2(63.33,18.21) ; R15.2 v2(78.56,59.29) ; R167.1 v2(7.82,60.5) ; C127.2 v2(60.29,55.17) ; R119.2 v2(9.16,46.65) ; C160.1 v2(30.58,31.93) ; C102.1 v2(52.13,27.86) ; P5.5 80.12,53.14 ; C188.2 v2(53.77,53.99) ; C158.1 v2(30.58,29.13) ; C136.2 v2(11.89,55.55) ; C52.1 v2(52.13,33.07) ; v2(2.24,55.3) 2.96,55.3 C129.2 ; C103.1 v2(52.13,29.13)
  vias: v1(16.64,4.11) v1(17.04,4.11) v1(17.86,59.61) v1(25.6,56.69) v1(31.45,63.55) v1(34.92,13.21) v1(35.92,8.21) v1(36.42,13.21) v1(37.97,65.58) v1(38.94,8.69) v1(39.45,9.19) v1(40.5,66.07) v1(42.62,65.46) v1(43.13,65.46) v1(54.46,42.42) v1(64.21,65.84) v1(69.82,65.38) v2(0.97,39.17) v2(0.97,35.61) v2(0.97,28.63) v2(0.97,23.42) v2(0.97,17.83) v2(1.22,61.14) v2(1.22,59.11) v2(1.22,55.04) v2(1.22,51.1) v2(1.22,7.16) v2(2.62,51.1) v2(2.62,49.96) v2(2.78,39.24) v2(2.78,38.61) v2(3.42,39.24) v2(3.42,38.61) v2(6.3,33.4) v2(6.43,50.22) v2(6.81,33.4) v2(6.93,50.22) v2(6.96,66.26) v2(6.96,65.57) v2(6.96,64.87) v2(7.32,33.4) v2(7.32,1.45) v2(7.44,50.22) v2(7.57,2.46) v2(7.66,66.26) v2(7.66,65.57) v2(7.66,64.87) v2(7.95,50.22) v2(8.36,66.26) v2(8.36,65.57) v2(8.36,64.87) v2(9.09,2.34) v2(9.35,33.4) v2(9.44,39.24) v2(9.44,38.61) v2(9.54,27.17) v2(9.54,26.59) v2(9.54,26.02) v2(9.73,14.66) v2(9.73,13.89) v2(9.73,13.13) v2(9.73,12.37) v2(9.73,11.61) v2(9.73,10.85) v2(9.73,9.58) v2(9.73,8.05) v2(9.86,33.4) v2(9.79,18.46) v2(9.79,17.83) v2(9.79,16.56) v2(9.79,15.92) v2(10.07,39.24) v2(10.07,38.61) v2(10.11,27.17) v2(10.11,26.59) v2(10.11,26.02) v2(10.36,33.4) v2(10.43,18.46) v2(10.43,17.83) v2(10.43,16.56) v2(10.43,15.92) v2(10.49,14.66) v2(10.49,13.89) v2(10.49,13.13) v2(10.49,12.37) v2(10.49,11.61) v2(10.49,10.85) v2(10.49,9.58) v2(10.49,8.05) v2(10.68,27.17) v2(10.68,26.59) v2(10.68,26.02) v2(10.74,1.45) v2(11.63,51.1) v2(11.63,49.96) v2(11.63,33.4) v2(11.89,47.04) v2(12.4,53.77) v2(12.9,33.4) v2(13.16,5.13) v2(13.41,33.4) v2(13.54,1.45) v2(13.92,33.4) v2(14.81,4.62) v2(15.95,35.99) v2(16.97,20.24) v2(16.97,18.97) v2(17.88,33.38) v2(18.24,26.91) v2(18.24,26.28) v2(18.36,49.33) v2(18.87,26.91) v2(18.87,26.28) v2(18.87,1.32) v2(20.02,1.32) v2(20.09,6.07) v2(20.65,32.82) v2(20.65,20.37) v2(20.65,19.35) v2(21.01,4.9) v2(21.16,32.82) v2(21.67,32.82) v2(21.67,20.37) v2(21.97,7.92) v2(22.28,61.54) v2(22.3,59.87) v2(22.68,32.82) v2(22.68,20.37) v2(22.68,19.35) v2(23.06,38.79) v2(23.06,37.01) v2(23.19,32.82) v2(23.42,60.3) v2(23.7,32.82) v2(23.7,20.37) v2(24.71,20.62) v2(25.25,52.02) v2(25.6,20.62) v2(25.6,19.86) v2(25.73,63.3) v2(25.83,52.02) v2(25.88,7.77) v2(26.11,1.45) v2(26.24,35.86) v2(26.54,40.26) v2(27.13,43.23) v2(27.43,8.31) v2(29.41,49.91) v2(29.54,24.31) v2(29.95,49.91) v2(30.81,1.45) v2(31.06,13.26) v2(31.06,5.38) v2(31.7,15.8) v2(31.83,22.02) v2(32.08,8.18) v2(32.33,1.32) v2(33.1,24.31) v2(33.86,5.38) v2(35.13,22.78) v2(36.02,1.19) v2(36.78,23.95) v2(37.54,2.84) v2(38.1,23.93) v2(39.07,3.35) v2(39.45,1.19) v2(40.59,15.04) v2(41.05,23.27) v2(41.1,2.59) v2(42.62,1.19) v2(43,22.45) v2(43.26,20.62) v2(43.26,18.34) v2(44.15,15.42) v2(44.46,5.19) v2(44.46,4.5) v2(44.46,3.8) v2(45.15,1.54) v2(45.16,5.19) v2(45.16,4.5) v2(45.16,3.8) v2(45.86,5.19) v2(45.86,4.5) v2(45.86,3.8) v2(47.22,23.95) v2(47.45,2.34) v2(47.45,1.54) v2(48.72,1.32) v2(50.62,25.07) v2(52.83,25.83) v2(53.04,1.19) v2(53.67,12.88) v2(54.94,60.63) v2(54.94,57.96) v2(54.88,37.45) v2(54.88,36.69) v2(54.88,35.93) v2(54.88,33.58) v2(54.88,30.21) v2(55.65,12.88) v2(56.41,37.24) v2(56.39,33.6) v2(56.39,31.27) v2(56.46,42.02) v2(56.91,45.52) v2(56.97,54.79) v2(56.97,54.15) v2(56.97,23.36) v2(56.97,22.72) v2(56.97,22.09) v2(56.97,21.45) v2(56.97,1.19) v2(57.35,63.42) v2(57.35,61.9) v2(57.35,60.38) v2(57.48,39.14) v2(57.48,37.59) v2(57.48,33.58) v2(57.48,31.29) v2(57.61,23.36) v2(57.61,22.72) v2(57.61,22.09) v2(57.61,21.45) v2(58.5,10.46) v2(59.05,12.45) v2(59.77,30.02) v2(60.02,31.93) v2(60.02,13.39) v2(60.15,36.88) v2(60.78,3.99) v2(60.78,1.19) v2(61.93,5.38) v2(62.43,27.74) v2(62.69,39.22) v2(62.69,3.99) v2(62.69,1.19) v2(63.07,34.59) v2(63.2,49.58) v2(63.2,42.34) v2(63.2,28.88) v2(63.32,39.22) v2(63.7,15.42) v2(63.83,26.34) v2(64.21,22.15) v2(64.44,62.38) v2(64.51,60.76) v2(65.35,55.3) v2(65.35,54.66) v2(65.35,54.03) v2(65.35,11.61) v2(65.74,19.23) v2(65.99,36.88) v2(65.99,31.93) v2(65.99,26.59) v2(66.29,62.61) v2(66.37,50.09) v2(66.5,42.34) v2(66.88,52.37) v2(66.88,40.69) v2(67.13,1.19) v2(67.16,25.31) v2(67.16,24.61) v2(67.16,23.91) v2(67.16,23.21) v2(67.16,22.51) v2(67.26,27.23) v2(67.64,43.1) v2(67.86,25.31) v2(67.86,24.61) v2(67.86,23.91) v2(67.86,23.21) v2(67.86,22.51) v2(68.28,33.96) v2(68.28,28.37) v2(68.4,57.84) v2(68.53,61.26) v2(68.56,25.31) v2(68.56,24.61) v2(68.56,23.91) v2(68.56,23.21) v2(68.56,22.51) v2(68.94,60.27) v2(68.91,53.01) v2(68.91,49.58) v2(69.24,55.93) v2(69.16,35.1) v2(69.26,25.31) v2(69.26,24.61) v2(69.26,23.91) v2(69.26,23.21) v2(69.42,46.91) v2(69.42,27.36) v2(69.52,12.12) v2(70.05,40.69) v2(70.05,30.28) v2(69.96,25.31) v2(69.96,24.61) v2(69.96,23.91) v2(69.96,23.21) v2(70.23,61.32) v2(70.56,1.19) v2(70.69,51.61) v2(70.69,26.59) v2(71.07,54.53) v2(71.58,42.34) v2(71.6,37.36) v2(71.7,49.71) v2(71.97,63.22) v2(71.96,23.8) v2(72.21,26.72) v2(72.34,25.32) v2(72.47,35.1) v2(72.47,10.59) v2(72.69,46.48) v2(73.23,54.15) v2(73.36,30.4) v2(73.61,49.68) v2(73.74,51.61) v2(74.52,50.5) v2(74.63,15.8) v2(74.75,54.41) v2(75.06,63.22) v2(75.26,1.57) v2(75.51,53.64) v2(75.51,37.77) v2(75.46,28.55) v2(75.51,23.29) v2(75.64,33.35) v2(75.9,15.67) v2(76.07,63.25) v2(76.28,14.4) v2(76.4,35.1) v2(76.66,22.4) v2(77.06,28.91) v2(77.24,58.19) v2(77.42,19.48) v2(77.55,15.67) v2(77.57,33.35) v2(77.7,56.85) v2(77.67,21.64) v2(79.07,34.34) v2(80.26,48.23) v2(80.34,7.8) v2(80.47,13) v2(80.59,42.47) v2(80.59,37.52) v2(80.72,61.14) v2(80.72,58.22) v2(80.72,55.3) v2(80.72,32.44) v2(80.72,27.86) v2(80.72,23.16) v2(80.72,18.97) v5(30.53,41.53) v5(30.53,39.52) v5(30.53,36.45) v5(35.18,36.88) v5(36.04,37.29) v5(36.07,40.08) v5(36.07,38.68) v5(37.77,38.56) v5(39.17,39.22) v5(39.17,37.74) v5(39.85,37.57) v5(40.41,38.51) v5(42.34,37.26) v5(43.38,40.82) v5(43.76,39.17) v5(43.76,37.26) v5(45.52,40.59) v5(45.54,39.17) v5(45.54,37.39) v5(48.11,35.28) v5(48.64,38.86) v5(48.72,36.65) v5(48.92,40.39) v5(50.32,40.39) v5(51.13,37.31) v5(51.1,36.04) v5(51.08,34.75) v5(52.15,36.3) v5(52.15,34.98) v5(52.15,33.71)
